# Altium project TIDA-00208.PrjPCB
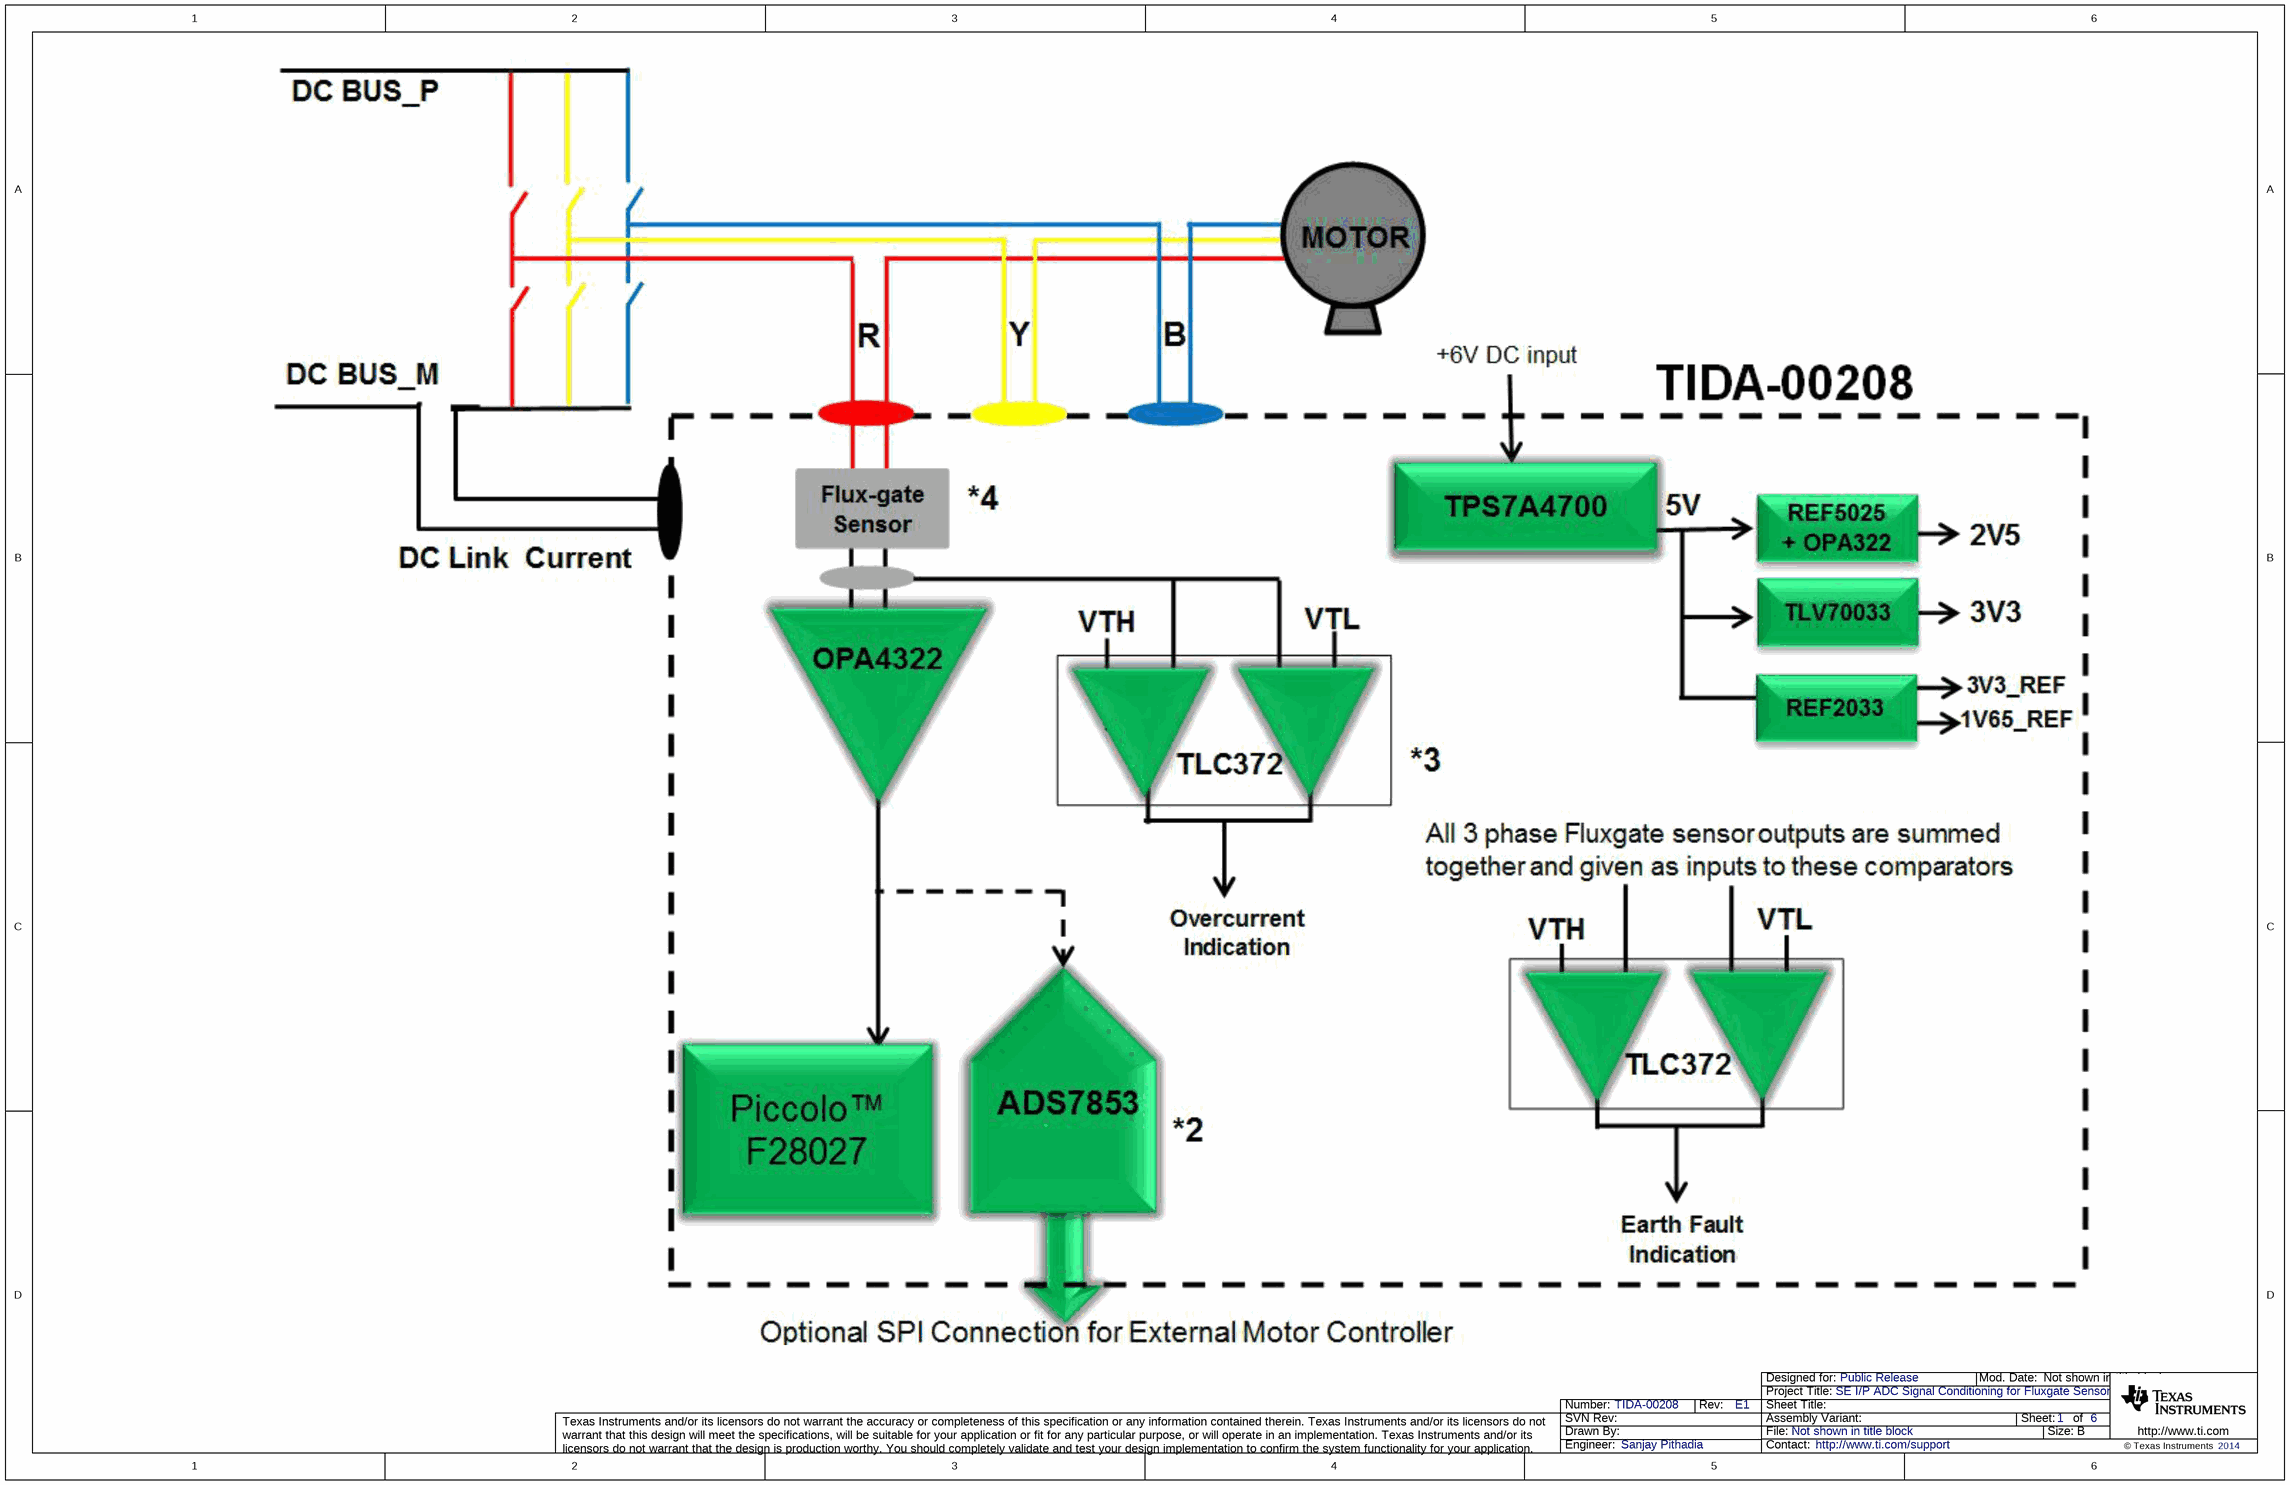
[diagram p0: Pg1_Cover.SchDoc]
TechSupport: http://www.ti.com/support; SCH_Rev: E1; PRJ_Title: SE I/P ADC Signal Conditioning for Fluxgate Sensor; PRJ_Number: TIDA-00208; PRJ_Engineer: Sanjay Pithadia; PRJ_Customer: Public Release; PCB_Rev: E2; PCB_Layout: Sharanu; CopyrightYear: 2014
6 sheets, 244 parts. Net scope: flat (ports and power ports of the same name join across sheets).
Board file: TIDA-00208.PcbDoc
Sheets:
  Pg1_Cover.SchDoc
  Pg2_Power.SchDoc
  Pg3_Channel-1_2.SchDoc
  Pg4_Channel-3_4.SchDoc
  Pg5_ADC - Connectors.SchDoc
  Pg6_Hardware_ANSI-B.SchDoc

## Sheet Pg1_Cover.SchDoc
size 431 x 279 mm; Date: Not shown in title block; ApprovedBy: Not shown in title block; CheckedBy: Not shown in title block; Author: Not shown in title block; CompanyName: Not shown in title block; Engineer: Not shown in title block; Organization: Not shown in title block; Address1: Not shown in title block; Address2: Not shown in title block; Address3: Not shown in title block; Address4: Not shown in title block; DocumentNumber: 1; Revision: Use project parameter SCH_Rev; SheetNumber: 1; SheetTotal: 6; PageSetup: Record=PageOptions|CenterHorizontal=True|CenterVertical=True|PrintScale=1.00|XCorrection=1.00|YCorrection=1.00|PrintKind=0|BorderSize=5000000|LeftOffset=0|BottomOffset=0|Orientation=2|PaperLength=1000|PaperWidth=1000|Scale=100|PaperSource=15|PrintQuality=600|MediaType=1|DitherType=10|PaperKind=Letter|PrintScaleMode=1

## Sheet Pg2_Power.SchDoc: Main
size 431 x 279 mm; Date: Not shown in title block; ApprovedBy: Not shown in title block; CheckedBy: Not shown in title block; Author: Not shown in title block; CompanyName: Not shown in title block; DrawnBy: Sanjay Pithadia; Engineer: Not shown in title block; Organization: Not shown in title block; Address1: Not shown in title block; Address2: Not shown in title block; Address3: Not shown in title block; Address4: Not shown in title block; DocumentNumber: 2; Revision: Use project parameter SCH_Rev; SheetNumber: 2; SheetTotal: 6; PageSetup: Record=PageOptions|CenterHorizontal=True|CenterVertical=True|PrintScale=1.00|XCorrection=1.00|YCorrection=1.00|PrintKind=0|BorderSize=5000000|LeftOffset=0|BottomOffset=0|Orientation=2|PaperLength=1000|PaperWidth=1000|Scale=100|PaperSource=15|PrintQuality=600|MediaType=1|DitherType=10|PaperKind=Letter|PrintScaleMode=1
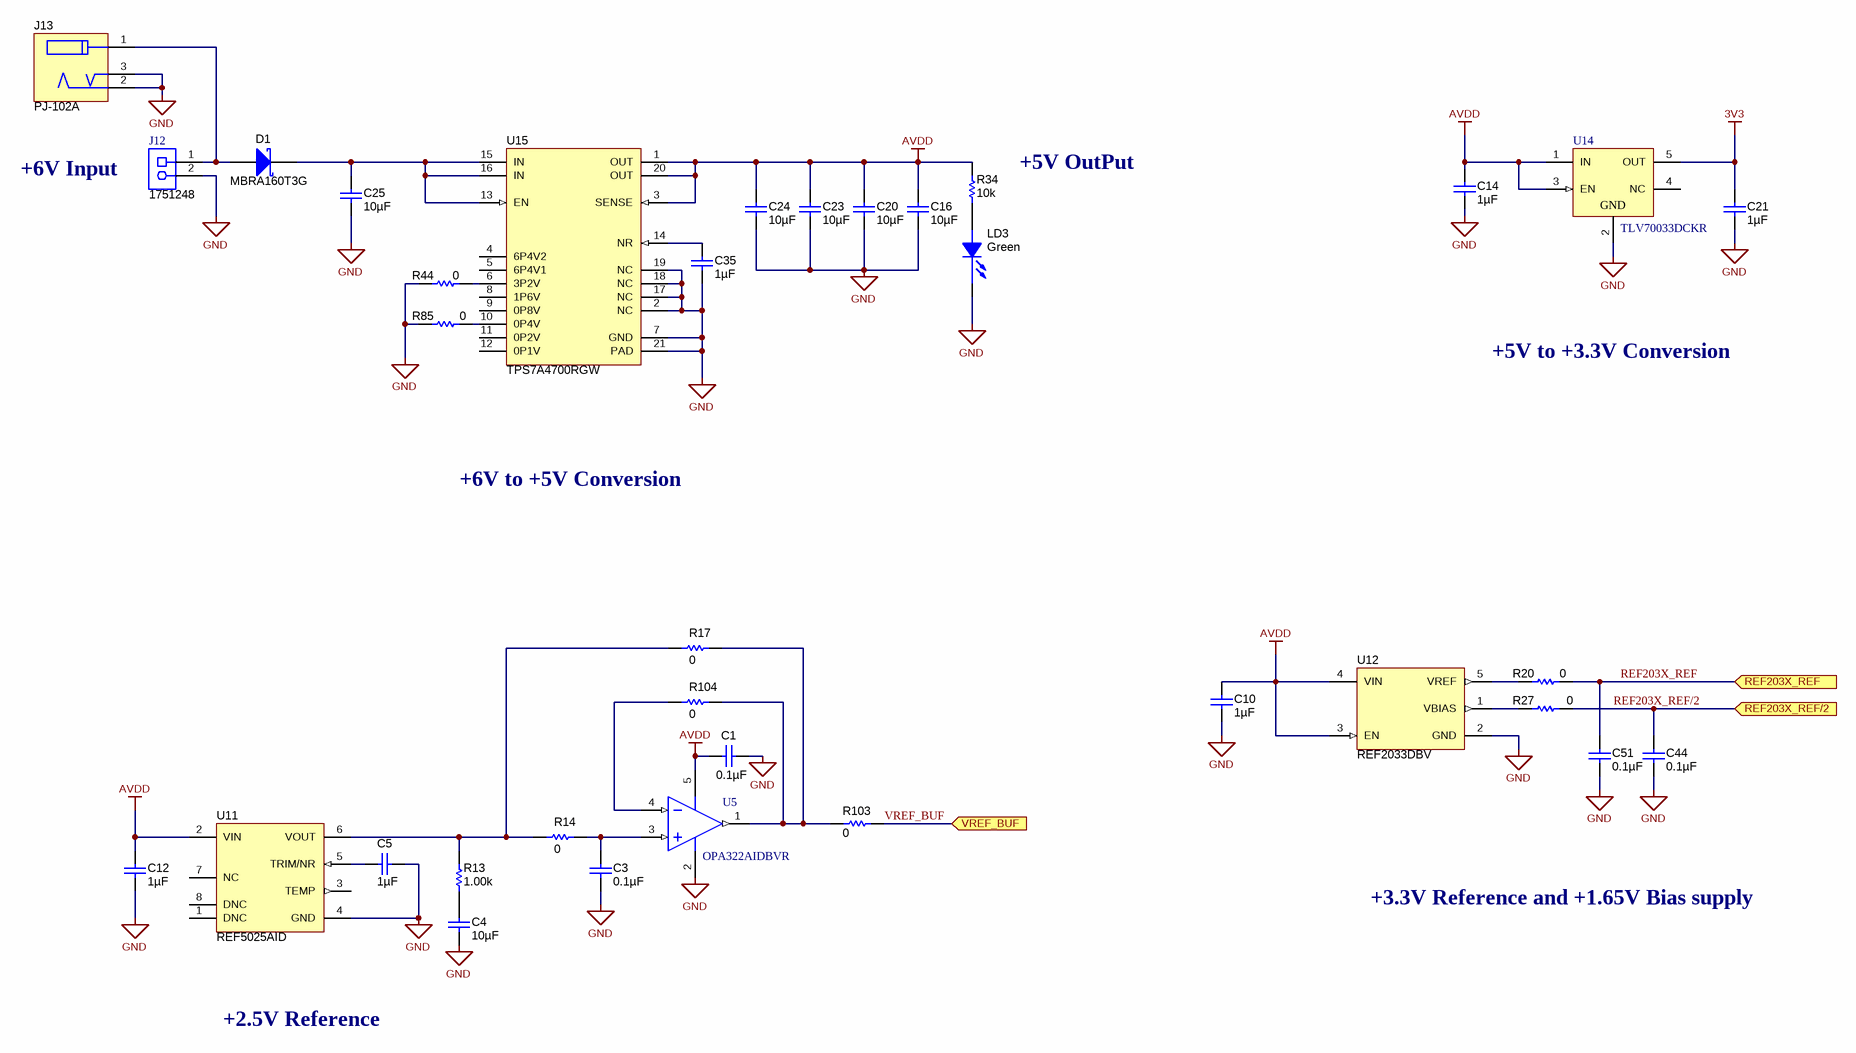
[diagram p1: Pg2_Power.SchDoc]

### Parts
C1  ValueDisplayed: 0.1µF  [0603]  (hidden comment: C0603C104J4RACTU)
C3  ValueDisplayed: 0.1µF  [0603]  (hidden comment: C0603C104K8RACTU)
C4  ValueDisplayed: 10µF  [0603]  (hidden comment: EMK107BBJ106MA-T)
C5  ValueDisplayed: 1µF  [0805_HV]  (hidden comment: C0805C105K8RACTU)
C10  ValueDisplayed: 1µF  [0805_HV]  (hidden comment: C0805C105K8RACTU)
C12  ValueDisplayed: 1µF  [0805_HV]  (hidden comment: C0805C105K8RACTU)
C14  ValueDisplayed: 1µF  [0805_HV]  (hidden comment: C0805C105K8RACTU)
C16  ValueDisplayed: 10µF  [0805_HV]  (hidden comment: GRM21BR61C106KE15L)
C20  ValueDisplayed: 10µF  [0805_HV]  (hidden comment: GRM21BR61C106KE15L)
C21  ValueDisplayed: 1µF  [0805_HV]  (hidden comment: C0805C105K8RACTU)
C23  ValueDisplayed: 10µF  [0805_HV]  (hidden comment: GRM21BR61C106KE15L)
C24  ValueDisplayed: 10µF  [0805_HV]  (hidden comment: GRM21BR61C106KE15L)
C25  ValueDisplayed: 10µF  [0805_HV]  (hidden comment: GRM21BR61C106KE15L)
C35  ValueDisplayed: 1µF  [0805_HV]  (hidden comment: C0805C105K8RACTU)
C44  ValueDisplayed: 0.1µF  [0603]  (hidden comment: C0603C104K8RACTU)
C51  ValueDisplayed: 0.1µF  [0603]  (hidden comment: C0603C104K8RACTU)
D1  MBRA160T3G  [SMA]
J12  1751248  [CONN_1751248]
J13  PJ-102A  [CONN_PJ-102A]
LD3  value Green  [LED0603AA]  (hidden comment: LED_LG L29K-G2J1-24-Z)
R13  value 1.00k  [0603]  (hidden comment: RC0603FR-071KL)
R14  value 0  [0603]  (hidden comment: CRCW06030000Z0EA)
R17  value 0  [0603]  (hidden comment: CRCW06030000Z0EA)
R20  value 0  [0603]  (hidden comment: CRCW06030000Z0EA)
R27  value 0  [0603]  (hidden comment: CRCW06030000Z0EA)
R34  value 10k  [0603]  (hidden comment: CRCW060310K0JNEA)
R44  value 0  [0603]  (hidden comment: CRCW06030000Z0EA)
R85  value 0  [0603]  (hidden comment: CRCW06030000Z0EA)
R103  value 0  [0603]  (hidden comment: CRCW06030000Z0EA)
R104  value 0  [0603]  (hidden comment: CRCW06030000Z0EA)
U5  OPA322AIDBVR  [DBV0005A_N]
U11  REF5025AID  [D0008A_N]
U12  REF2033DBV  [DBV0005A_N]
U14  TLV70033DCKR  [DCK0005A_N]
U15  TPS7A4700RGW  [RGW0020A]

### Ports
REF203X_REF (in), REF203X_REF/2 (in), VREF_BUF (in)

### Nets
3V3: C21.1 U14.5(OUT)
AVDD: C1.2 C10.1 C12.1 C14.1 C16.1 C20.1 C23.1 C24.1 R34.2 U5.5(V+) U11.2(VIN) U12.3(EN) U12.4(VIN) U14.1(IN) U14.3(EN) U15.1(OUT) U15.3(SENSE) U15.20(OUT)
GND: C1.1 C3.1 C4.2 C5.2 C10.2 C12.2 C14.2 C16.2 C20.2 C21.2 C23.2 C24.2 C25.2 C35.1 C44.1 C51.1 J12.2 J13.2 J13.3 LD3.1(C) R44.1 R85.2 U5.2(V-) U11.4(GND) U12.2(GND) U14.2(GND) U15.2(NC) U15.7(GND) U15.17(NC) U15.18(NC) U15.19(NC) U15.21(PAD)
REF203X_REF: C51.2 R20.1 ; port REF203X_REF
REF203X_REF/2: C44.2 R27.1 ; port REF203X_REF/2
VREF_BUF: R103.1 ; port VREF_BUF
NetC3_2: C3.2 R14.1 U5.3(IN+)
NetC4_1: C4.1 R13.1
NetC5_1: C5.1 U11.5(TRIM/NR)
NetC25_1: C25.1 D1.1(K) U15.13(EN) U15.15(IN) U15.16(IN)
NetC35_2: C35.2 U15.14(NR)
NetD1_2: D1.2(A) J12.1 J13.1
NetLD3_2: LD3.2(A) R34.1
NetR13_2: R13.2 R14.2 R17.2 U11.6(VOUT)
NetR17_1: R17.1 R103.2 R104.1 U5.1(OUT)
NetR20_2: R20.2 U12.5(VREF)
NetR27_2: R27.2 U12.1(VBIAS)
NetR44_2: R44.2 U15.6(3P2V)
NetR85_1: R85.1 U15.10(0P4V)
NetR104_2: R104.2 U5.4(IN-)

Not connected (* = marked no-connect by the designer): U11 1(DNC) 3(TEMP) 7(NC) 8(DNC); U14 4(NC); U15 4(6P4V2) 5(6P4V1) 8(1P6V) 9(0P8V) 11(0P2V) 12(0P1V)

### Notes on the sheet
- +6V Input
- +5V OutPut
- +5V to +3.3V Conversion
- +6V to +5V Conversion
- +3.3V Reference and +1.65V Bias supply
- +2.5V Reference

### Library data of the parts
C1 = C0603C104J4RACTU: CAP, CERM, 0.1uF, 16V, +/-5%, X7R, 0603; Manufacturer: Kemet; Polarized: N; CompType: Capacitor; U/M: EA; Cap_F: 0.0000001; Tolerance_%: 5; Value1: Unknown; VDC_V: 16; TaMin_C: -55; TaMax_C: 125
C3 C44 C51 = C0603C104K8RACTU: CAP, CERM, 0.1uF, 10V, +/-10%, X7R, 0603; Manufacturer: Kemet; Polarized: N; CompType: Capacitor; U/M: EA; Cap_F: 0.0000001; Tolerance_%: 10; Value1: Unknown; TaMin_C: -55; TaMax_C: 125
C4 = EMK107BBJ106MA-T: CAP, CERM, 10uF, 16V, +/-20%, X5R, 0603; Manufacturer: Taiyo Yuden; Polarized: N; CompType: Capacitor; U/M: EA; Cap_F: 0.00001; Tolerance_%: 20; Value1: Unknown; VDC_V: 16; TaMin_C: -55; TaMax_C: 85
C5 C10 C12 C14 C21 C35 = C0805C105K8RACTU: CAP, CERM, 1uF, 10V, +/-10%, X7R, 0805; Manufacturer: Kemet; Polarized: N; CompType: Capacitor; U/M: EA; Cap_F: 0.000001; Tolerance_%: 10; ESR_Ohm: 0.015; Value1: 0.015 ohm; IRMS_A: 8.19; TaMin_C: -55; TaMax_C: 125; Cap_Case: 0805
C16 C20 C23-C25 = GRM21BR61C106KE15L: CAP, CERM, 10uF, 16V, +/-10%, X5R, 0805; Manufacturer: MuRata; Polarized: N; CompType: Capacitor; U/M: EA; Cap_F: 0.00001; Tolerance_%: 10; ESR_Ohm: 0.008; Value1: 0.008 ohm; VDC_V: 16; TaMin_C: -55; TaMax_C: 85; Cap_Case: 0805
D1 = MBRA160T3G: Diode, Schottky, 60V, 1A, SMA; Manufacturer: ON Semiconductor; U/M: EA; Vf_V: 0.51; Value2: 0.51V; Io_A: 1; Vr_V: 60; TJmax_C: 150; RJC_CperW: 35
J12 = 1751248: Conn Term Block, 2POS, 3.5mm, TH; Manufacturer: Phoenix Contact; SymbolCreator: a0412235; Value: 2x1; CompType: Terminal Block; U/M: EA
J13 = PJ-102A: Connector, DC Jack 2.1X5.5 mm, TH; Manufacturer: CUI Inc.; SymbolCreator: a0799628; U/M: EA
LD3 = LED_LG L29K-G2J1-24-Z: LED SmartLED Green 570NM; Manufacturer: OSRAM; SymbolCreator: x0120606
R13 = RC0603FR-071KL: RES, 1.00k ohm, 1%, 0.1W, 0603; Manufacturer: Yageo America; CompType: Resistor; Res_ohm: 1000; Value_Code: 1k00; Tolerance_%: 1; Power_W: 0.1; VDC_V: 150; TempCo: 200 ppm/C; EIA_Code: E96; U/M: EA
R14 R17 R20 R27 R44 R85 R103 R104 = CRCW06030000Z0EA: RES, 0 ohm, 5%, 0.1W, 0603; Manufacturer: Vishay-Dale; CompType: Resistor; Value_Code: 0000; Tolerance_%: 5; Power_W: 0.1; VDC_V: 75; TempCo: 200 ppm/C; EIA_Code: E24; U/M: EA
R34 = CRCW060310K0JNEA: RES, 10k ohm, 5%, 0.1W, 0603; Manufacturer: Vishay-Dale; CompType: Resistor; Res_ohm: 10000; Value_Code: 10k0; Tolerance_%: 5; Power_W: 0.1; VDC_V: 75; TempCo: 200 ppm/C; EIA_Code: E24; U/M: EA
U5 = OPA322AIDBVR: 20 MHz, Low Noise, RRIO, CMOS Operational Amplifier with Shutdown, 1.8 to 5.5 V, -40 to 125 degC, 5-pin SOT23 (DBV0005A), Green (RoHS & no Sb/Br); Manufacturer: Texas Instruments; Alternate Manufacturer: None; Alternate PartNumber: Equivalent; CMRR(Min)(dB): 90; GBW(Typ)(MHz): 20; IIB(Max)(pA): 10; Iq per channel(Max)(mA): 1.9; Number of Channels: 1; Offset Drift(Typ)(uV/C): 1.8; Packing: LARGE T&R; Rating: Catalog; Sub Family: High Output Current Amplifier (>=50mA), Low Input Bias Current Amp (<=10pA), Low Noise Amp (<=10nV/rtHz), Low Supply Voltage Amplifier (<=2.7V), Precision Amplifier; Total Supply Voltage(Max)(+5V is 5, +/-5V is 10): 5.5; Vio (25C)(Max)(mV): 2
U11 = REF5025AID: Low-Noise, Very Low Drift, Precision VOLTAGE REFERENCE, 2.5V, D008A; Alternate Manufacturer: None; Manufacturer: Texas Instruments; SymbolCreator: a0411947; CompType: IC; U/M: EA
U12 = REF2033DBV: DUAL OUTPUT VOLTAGE REFERENCE 3.3V, DBV0005A; Alternate Manufacturer: None; Manufacturer: Texas Instruments; SymbolCreator: a0799628; CompType: IC; U/M: EA
U14 = TLV70033DCKR: Single Output LDO, 200 mA, Fixed 3.3 V Output, 2 to 5.5 V Input, with Low IQ, 5-pin SC70 (DCK), -40 to 125 degC, Green (RoHS & no Sb/Br); Manufacturer: Texas Instruments; Alternate Manufacturer: None; Alternate PartNumber: Equivalent; Accuracy(%): 2; Fixed Output Options(V): 3.3; Iout(Max)(A): 0.2; Iq(Typ)(mA): 0.03; SubFamily: Single Channel LDO; Vdo(Typ)(mV): 175; Vin(Max)(V): 5.5
U15 = TPS7A4700RGW: 36-V, 1-A, 4.17-µVRMS, RF LDO Voltage Regulator, RGW0020A; Alternate Manufacturer: None; Manufacturer: Texas Instruments; SymbolCreator: a0412235; CompType: IC; U/M: EA

## Sheet Pg3_Channel-1_2.SchDoc: Main
size 431 x 279 mm; Date: Not shown in title block; ApprovedBy: Not shown in title block; CheckedBy: Not shown in title block; Author: Not shown in title block; CompanyName: Not shown in title block; DrawnBy: Sanjay Pithadia; Engineer: Not shown in title block; Organization: Not shown in title block; Address1: Not shown in title block; Address2: Not shown in title block; Address3: Not shown in title block; Address4: Not shown in title block; DocumentNumber: 3; Revision: Use project parameter SCH_Rev; SheetNumber: 3; SheetTotal: 6; PageSetup: Record=PageOptions|CenterHorizontal=True|CenterVertical=True|PrintScale=1.00|XCorrection=1.00|YCorrection=1.00|PrintKind=0|BorderSize=5000000|LeftOffset=0|BottomOffset=0|Orientation=2|PaperLength=1000|PaperWidth=1000|Scale=100|PaperSource=15|PrintQuality=600|MediaType=1|DitherType=10|PaperKind=Letter|PrintScaleMode=1
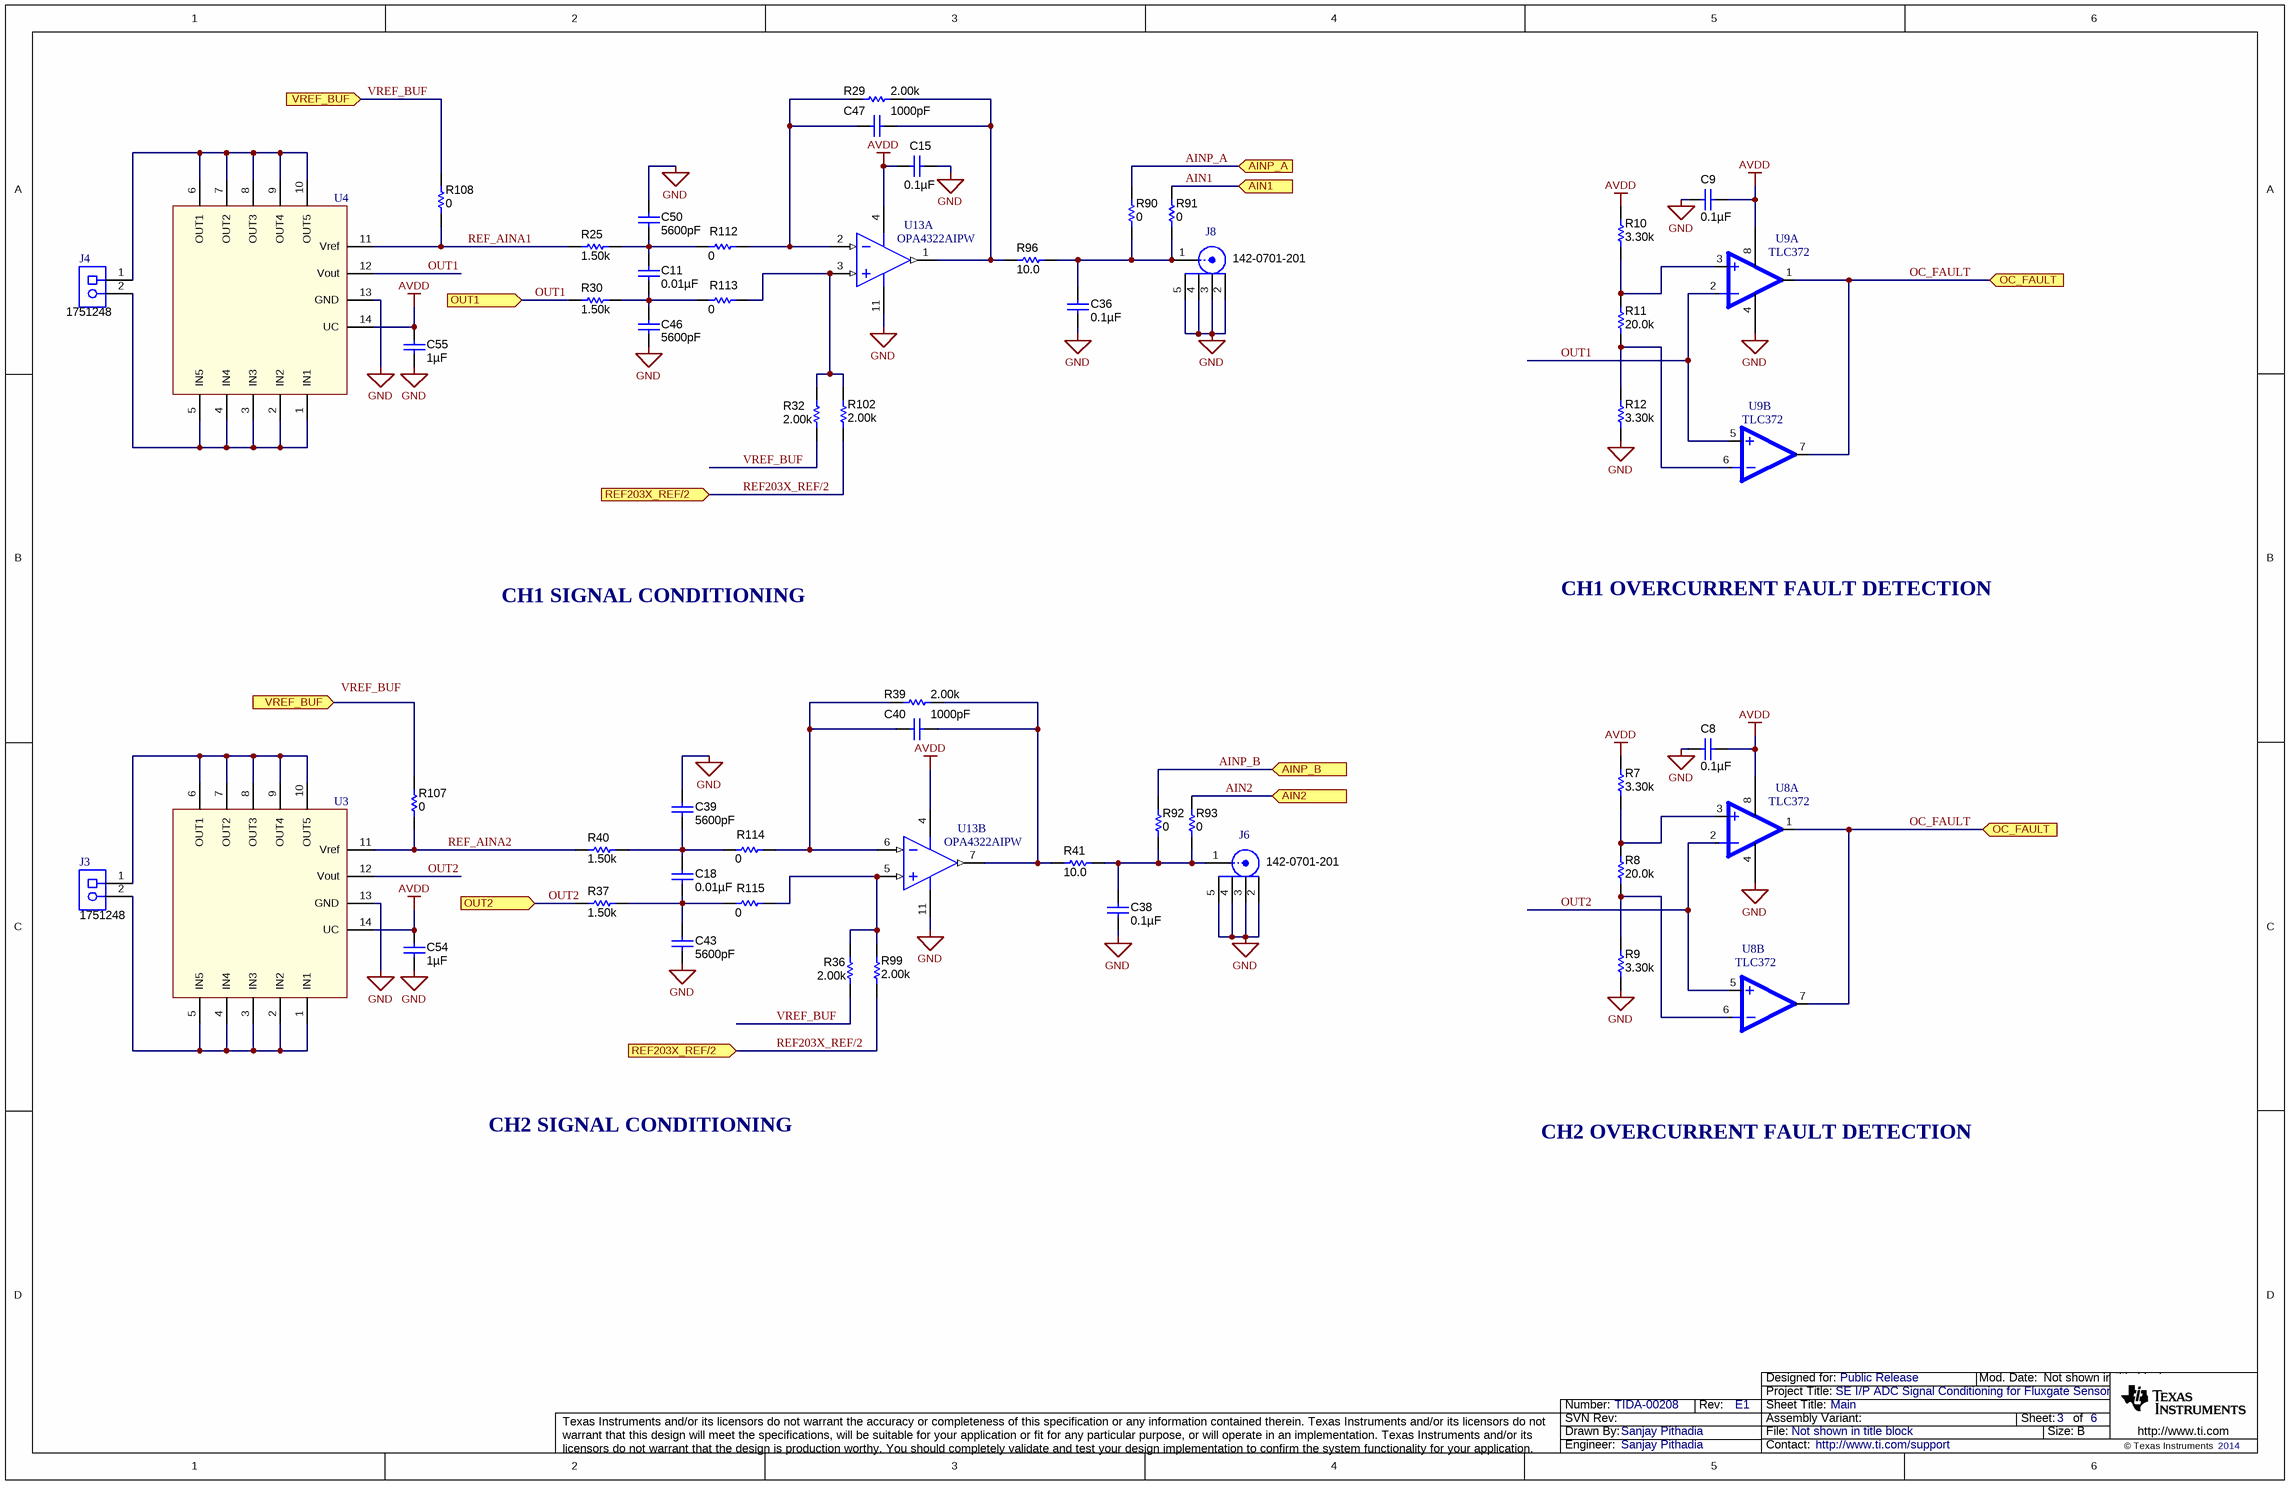
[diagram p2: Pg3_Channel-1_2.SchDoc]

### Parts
C8  ValueDisplayed: 0.1µF  [0603]  (hidden comment: C0603C104J4RACTU)
C9  ValueDisplayed: 0.1µF  [0603]  (hidden comment: C0603C104J4RACTU)
C11  ValueDisplayed: 0.01µF  [0603]  (hidden comment: C0603H103J3GACTU)
C15  ValueDisplayed: 0.1µF  [0603]  (hidden comment: C0603C104J4RACTU)
C18  ValueDisplayed: 0.01µF  [0603]  (hidden comment: C0603H103J3GACTU)
C36  ValueDisplayed: 0.1µF  [0603]  (hidden comment: C0603C104J4RACTU)
C38  ValueDisplayed: 0.1µF  [0603]  (hidden comment: C0603C104J4RACTU)
C39  ValueDisplayed: 5600pF  [0603]  (hidden comment: C1608C0G1E562J)
C40  ValueDisplayed: 1000pF  [0603]  (hidden comment: GRM1885C1E102JA01D)
C43  ValueDisplayed: 5600pF  [0603]  (hidden comment: C1608C0G1E562J)
C46  ValueDisplayed: 5600pF  [0603]  (hidden comment: C1608C0G1E562J)
C47  ValueDisplayed: 1000pF  [0603]  (hidden comment: GRM1885C1E102JA01D)
C50  ValueDisplayed: 5600pF  [0603]  (hidden comment: C1608C0G1E562J)
C54  ValueDisplayed: 1µF  [0603]  (hidden comment: GRM188R71E105KA12D)
C55  ValueDisplayed: 1µF  [0603]  (hidden comment: GRM188R71E105KA12D)
J3  1751248  [CONN_1751248]
J4  1751248  [CONN_1751248]
J6  142-0701-201  [Johnson_142-0701-20x]
J8  142-0701-201  [Johnson_142-0701-20x]
R7  value 3.30k  [0603]  (hidden comment: RC0603FR-073K3L)
R8  value 20.0k  [0603]  (hidden comment: CRCW060320K0FKEA)
R9  value 3.30k  [0603]  (hidden comment: RC0603FR-073K3L)
R10  value 3.30k  [0603]  (hidden comment: RC0603FR-073K3L)
R11  value 20.0k  [0603]  (hidden comment: CRCW060320K0FKEA)
R12  value 3.30k  [0603]  (hidden comment: RC0603FR-073K3L)
R25  ValueDisplayed: 1.50k  [0603]  (hidden comment: CRCW06031K50FKEA)
R29  ValueDisplayed: 2.00k  [0603]  (hidden comment: CRCW06032K00FKEA)
R30  ValueDisplayed: 1.50k  [0603]  (hidden comment: CRCW06031K50FKEA)
R32  ValueDisplayed: 2.00k  [0603]  (hidden comment: CRCW06032K00FKEA)
R36  ValueDisplayed: 2.00k  [0603]  (hidden comment: CRCW06032K00FKEA)
R37  ValueDisplayed: 1.50k  [0603]  (hidden comment: CRCW06031K50FKEA)
R39  ValueDisplayed: 2.00k  [0603]  (hidden comment: CRCW06032K00FKEA)
R40  ValueDisplayed: 1.50k  [0603]  (hidden comment: CRCW06031K50FKEA)
R41  value 10.0  [0603]  (hidden comment: RT0603BRD0710RL)
R90  value 0  [0603]  (hidden comment: CRCW06030000Z0EA)
R91  value 0  [0603]  (hidden comment: CRCW06030000Z0EA)
R92  value 0  [0603]  (hidden comment: CRCW06030000Z0EA)
R93  value 0  [0603]  (hidden comment: CRCW06030000Z0EA)
R96  value 10.0  [0603]  (hidden comment: RT0603BRD0710RL)
R99  ValueDisplayed: 2.00k  [0603]  (hidden comment: CRCW06032K00FKEA)
R102  ValueDisplayed: 2.00k  [0603]  (hidden comment: CRCW06032K00FKEA)
R107  value 0  [0603]  (hidden comment: CRCW06030000Z0EA)
R108  value 0  [0603]  (hidden comment: CRCW06030000Z0EA)
R112  value 0  [0603]  (hidden comment: CRCW06030000Z0EA)
R113  value 0  [0603]  (hidden comment: CRCW06030000Z0EA)
R114  value 0  [0603]  (hidden comment: CRCW06030000Z0EA)
R115  value 0  [0603]  (hidden comment: CRCW06030000Z0EA)
U3  SENSOR_CKSR X-NP  [CKSR X-NP]  (value not drawn)
U4  SENSOR_CKSR X-NP  [CKSR X-NP]  (value not drawn)
U8  TLC372  [SO8]  (parts A,B of 2)
U9  TLC372  [SO8]  (parts A,B of 2)
U13  OPA4322AIPW  [PW0014A_N]  (parts A,B of 4)

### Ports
AIN1 (in), AIN2 (in), AINP_A (in), AINP_B (in), OC_FAULT (in), OUT1 (in), OUT2 (in), REF203X_REF/2 (in), VREF_BUF (in)

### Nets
AVDD: C8.1 C9.1 C15.2 C54.2 C55.2 R7.2 R10.2 U3.14(UC) U4.14(UC) U8.8(VCC) U9.8(VCC) U13.4(V+)
GND: C8.2 C9.2 C15.1 C36.2 C38.2 C39.2 C43.2 C46.2 C50.2 C54.1 C55.1 J6.2 J6.3 J6.4 J6.5 J8.2 J8.3 J8.4 J8.5 R9.1 R12.1 U3.13(GND) U4.13(GND) U8.4(GND) U9.4(GND) U13.11(V-)
AIN1: R91.2 ; port AIN1
AIN2: R93.2 ; port AIN2
AINP_A: R90.2 ; port AINP_A
AINP_B: R92.2 ; port AINP_B
OC_FAULT: U8.1(OUT) U8.7(OUT) U9.1(OUT) U9.7(OUT) ; port OC_FAULT
OUT1: R30.1 U4.12(Vout) U9.2(IN-) U9.5(IN+) ; port OUT1
OUT2: R37.1 U3.12(Vout) U8.2(IN-) U8.5(IN+) ; port OUT2
REF203X_REF/2: R99.1 R102.1 ; port REF203X_REF/2
REF_AINA1: R25.1 R108.1 U4.11(Vref)
REF_AINA2: R40.1 R107.1 U3.11(Vref)
VREF_BUF: R32.1 R36.1 R107.2 R108.2 ; port VREF_BUF
NetC11_1: C11.1 C46.1 R30.2 R113.2
NetC11_2: C11.2 C50.1 R25.2 R112.2
NetC18_1: C18.1 C39.1 R40.2 R114.2
NetC18_2: C18.2 C43.1 R37.2 R115.2
NetC36_1: C36.1 J8.1 R90.1 R91.1 R96.2
NetC38_1: C38.1 J6.1 R41.2 R92.1 R93.1
NetC40_1: C40.1 R39.2 R41.1 U13.7(OUT_B)
NetC40_2: C40.2 R39.1 R114.1 U13.6(IN_B-)
NetC47_1: C47.1 R29.2 R96.1 U13.1(OUT_A)
NetC47_2: C47.2 R29.1 R112.1 U13.2(IN_A-)
NetJ3_1: J3.1 U3.6(OUT1) U3.7(OUT2) U3.8(OUT3) U3.9(OUT4) U3.10(OUT5)
NetJ3_2: J3.2 U3.1(IN1) U3.2(IN2) U3.3(IN3) U3.4(IN4) U3.5(IN5)
NetJ4_1: J4.1 U4.6(OUT1) U4.7(OUT2) U4.8(OUT3) U4.9(OUT4) U4.10(OUT5)
NetJ4_2: J4.2 U4.1(IN1) U4.2(IN2) U4.3(IN3) U4.4(IN4) U4.5(IN5)
NetR7_1: R7.1 R8.2 U8.3(IN+)
NetR8_1: R8.1 R9.2 U8.6(IN-)
NetR10_1: R10.1 R11.2 U9.3(IN+)
NetR11_1: R11.1 R12.2 U9.6(IN-)
NetR32_2: R32.2 R102.2 R113.1 U13.3(IN_A+)
NetR36_2: R36.2 R99.2 R115.1 U13.5(IN_B+)

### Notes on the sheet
- CH1 SIGNAL CONDITIONING
- CH1 OVERCURRENT FAULT DETECTION
- CH2 SIGNAL CONDITIONING
- CH2 OVERCURRENT FAULT DETECTION
- Labels drawn without touching a wire or pin: VREF_BUF

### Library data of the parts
C8 C9 C15 C36 C38 = C0603C104J4RACTU: as C1 on sheet Pg2_Power
C11 C18 = C0603H103J3GACTU: CAP, CERM, 0.01uF, 25V, +/-5%, C0G/NP0, 0603; Manufacturer: Kemet; Polarized: N; CompType: Capacitor; U/M: EA; Cap_F: 0.00000001; Tolerance_%: 5; Value1: Unknown; VDC_V: 25; TaMin_C: -55; TaMax_C: 200
C39 C43 C46 C50 = C1608C0G1E562J: CAP, CERM, 5600pF, 25V, +/-5%, C0G/NP0, 0603; Manufacturer: TDK; Polarized: N; CompType: Capacitor; U/M: EA; Cap_F: 0.0000000056; Tolerance_%: 5; Value1: Unknown; VDC_V: 25; TaMin_C: -55; TaMax_C: 125
C40 C47 = GRM1885C1E102JA01D: CAP, CERM, 1000pF, 25V, +/-5%, C0G/NP0, 0603; Manufacturer: MuRata; Polarized: N; CompType: Capacitor; U/M: EA; Cap_F: 0.000000001; Tolerance_%: 5; Value1: Unknown; VDC_V: 25; TaMin_C: -55; TaMax_C: 125
C54 C55 = GRM188R71E105KA12D: CAP, CERM, 1uF, 25V, +/-10%, X7R, 0603; Manufacturer: MuRata; Polarized: N; CompType: Capacitor; U/M: EA; Cap_F: 0.000001; Tolerance_%: 10; Value1: Unknown; VDC_V: 25; TaMin_C: -55; TaMax_C: 125
J3 J4 = 1751248: as J12 on sheet Pg2_Power
J6 J8 = 142-0701-201: Connector, TH, SMA; Manufacturer: Emerson Network Power; SymbolCreator: X0208326; U/M: EA
R7 R9 R10 R12 = RC0603FR-073K3L: RES, 3.30k ohm, 1%, 0.1W, 0603; Manufacturer: Yageo America; CompType: Resistor; Res_ohm: 3300; Value_Code: 3k30; Tolerance_%: 1; Power_W: 0.1; VDC_V: 150; TempCo: 200 ppm/C; U/M: EA
R8 R11 = CRCW060320K0FKEA: RES, 20.0k ohm, 1%, 0.1W, 0603; Manufacturer: Vishay-Dale; CompType: Resistor; Res_ohm: 20000; Value_Code: 20k0; Tolerance_%: 1; Power_W: 0.1; VDC_V: 75; TempCo: 100 ppm/C; EIA_Code: E96; U/M: EA
R25 R30 R37 R40 = CRCW06031K50FKEA: RES, 1.50 k, 1%, 0.1 W, 0603; Manufacturer: Vishay-Dale; CompType: Resistor; Value: 1.50k; Res_ohm: 1500; Value_Code: 1k50; Tolerance_%: 1; Power_W: 0.1; Value2: 0.1W; VDC_V: 75; TempCo: 100 ppm/C; EIA_Code: E96; U/M: EA
R29 R32 R36 R39 R99 R102 = CRCW06032K00FKEA: RES, 2.00 k, 1%, 0.1 W, 0603; Manufacturer: Vishay-Dale; CompType: Resistor; Value: 2.00k; Res_ohm: 2000; Value_Code: 2k00; Tolerance_%: 1; Power_W: 0.1; Value2: 0.1W; VDC_V: 75; TempCo: 100 ppm/C; EIA_Code: E96; U/M: EA
R41 R96 = RT0603BRD0710RL: RES, 10.0 ohm, 0.1%, 0.1W, 0603; Manufacturer: Yageo America; CompType: Resistor; Res_ohm: 10; Value_Code: 10R0; Tolerance_%: 0.1; VDC_V: 75; TempCo: 25 ppm/C; EIA_Code: E192; U/M: EA
R90-R93 R107 R108 R112-R115 = CRCW06030000Z0EA: as R14 on sheet Pg2_Power
U3 U4 = SENSOR_CKSR X-NP: SENSOR CURRENT 50A 5V MOD; Manufacturer: LEM USA Inc; CompType: Current Transducers
U8 U9 = LM393D: IC, Dual Differential Comparators, 2-36 Vin; Manufacturer: TI; Alternate Manufacturer: None; Area: 75900
U13 = OPA4322AIPW: 20 MHz, Low Noise, RRIO, CMOS Operational Amplifier, 1.8 to 5.5 V, -40 to 125 degC, 14-pin SOP (PW0014A), Green (RoHS & no Sb/Br); Manufacturer: Texas Instruments; Alternate Manufacturer: None; Alternate PartNumber: Equivalent; CMRR(Min)(dB): 90; GBW(Typ)(MHz): 20; IIB(Max)(pA): 10; Iq per channel(Max)(mA): 1.65; Number of Channels: 4; Offset Drift(Typ)(uV/C): 1.8; Packing: TUBE; Rating: Catalog; Sub Family: High Output Current Amplifier (>=50mA), Low Input Bias Current Amp (<=10pA), Low Noise Amp (<=10nV/rtHz), Low Supply Voltage Amplifier (<=2.7V), Precision Amplifier; Total Supply Voltage(Max)(+5V is 5, +/-5V is 10): 5.5; Vio (25C)(Max)(mV): 2

## Sheet Pg4_Channel-3_4.SchDoc: Main
size 431 x 279 mm; Date: Not shown in title block; ApprovedBy: Not shown in title block; CheckedBy: Not shown in title block; Author: Not shown in title block; CompanyName: Not shown in title block; DrawnBy: Sanjay Pithadia; Engineer: Not shown in title block; Organization: Not shown in title block; Address1: Not shown in title block; Address2: Not shown in title block; Address3: Not shown in title block; Address4: Not shown in title block; DocumentNumber: 4; Revision: Use project parameter SCH_Rev; SheetNumber: 4; SheetTotal: 6; PageSetup: Record=PageOptions|CenterHorizontal=True|CenterVertical=True|PrintScale=1.00|XCorrection=1.00|YCorrection=1.00|PrintKind=0|BorderSize=5000000|LeftOffset=0|BottomOffset=0|Orientation=2|PaperLength=1000|PaperWidth=1000|Scale=100|PaperSource=15|PrintQuality=600|MediaType=1|DitherType=10|PaperKind=Letter|PrintScaleMode=1
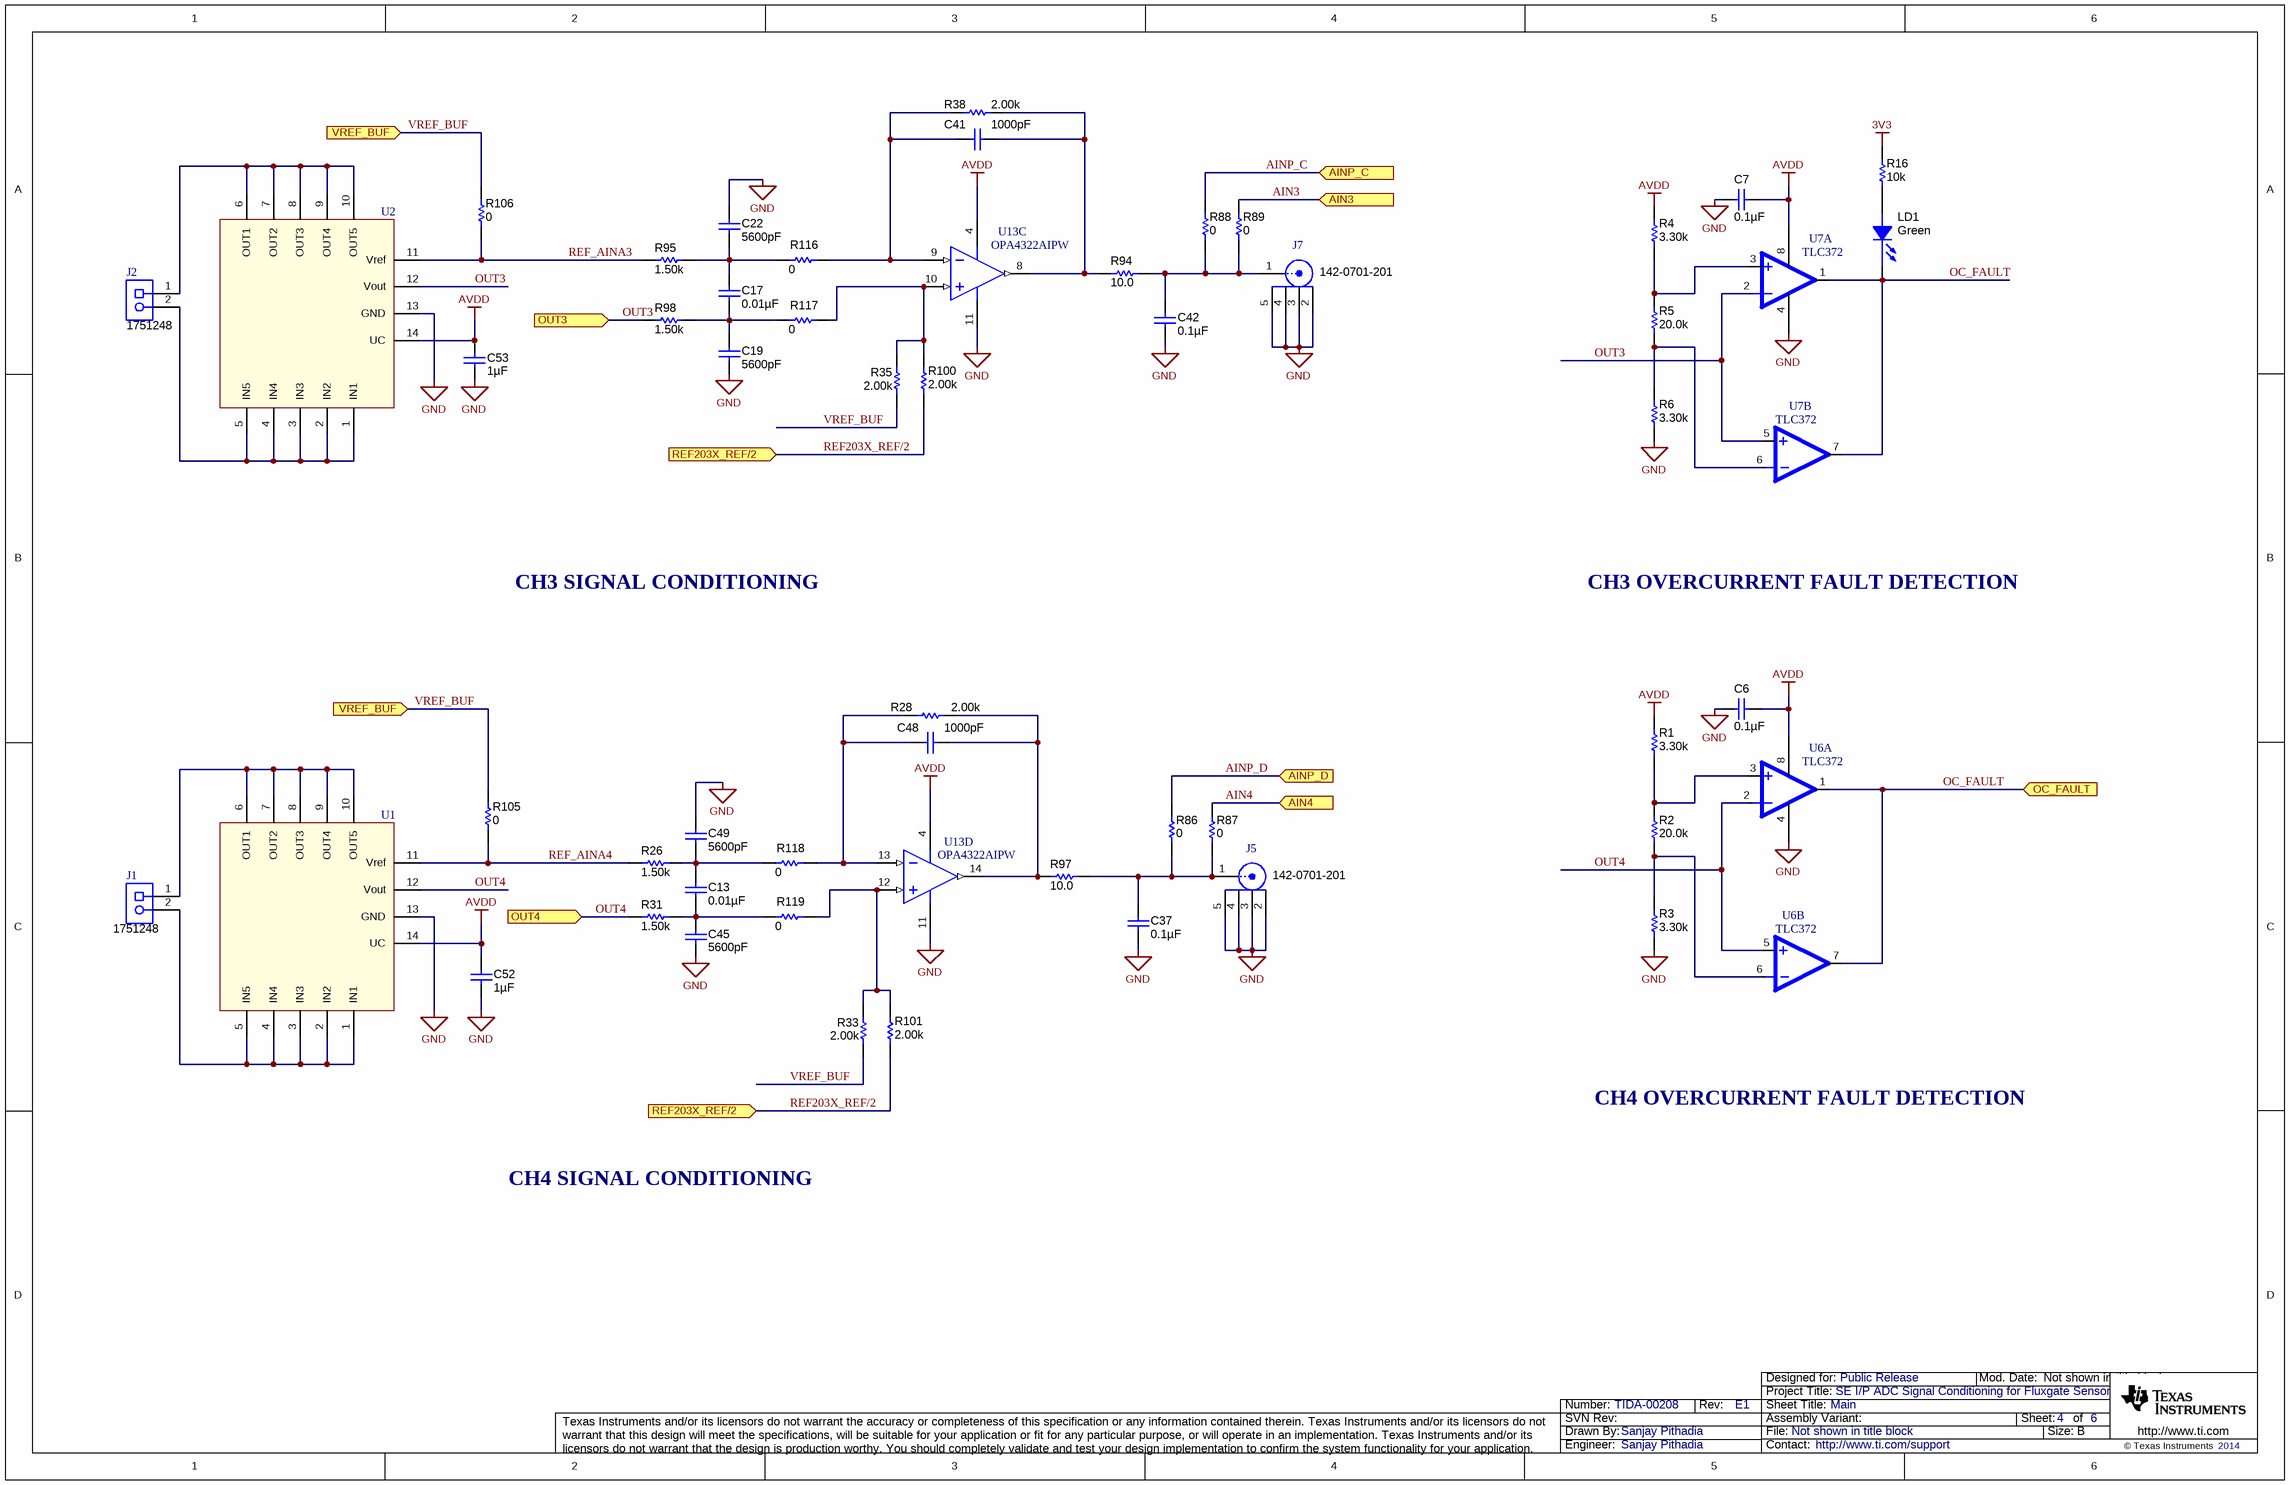
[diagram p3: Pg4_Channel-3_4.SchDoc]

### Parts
C6  ValueDisplayed: 0.1µF  [0603]  (hidden comment: C0603C104J4RACTU)
C7  ValueDisplayed: 0.1µF  [0603]  (hidden comment: C0603C104J4RACTU)
C13  ValueDisplayed: 0.01µF  [0603]  (hidden comment: C0603H103J3GACTU)
C17  ValueDisplayed: 0.01µF  [0603]  (hidden comment: C0603H103J3GACTU)
C19  ValueDisplayed: 5600pF  [0603]  (hidden comment: C1608C0G1E562J)
C22  ValueDisplayed: 5600pF  [0603]  (hidden comment: C1608C0G1E562J)
C37  ValueDisplayed: 0.1µF  [0603]  (hidden comment: C0603C104J4RACTU)
C41  ValueDisplayed: 1000pF  [0603]  (hidden comment: GRM1885C1E102JA01D)
C42  ValueDisplayed: 0.1µF  [0603]  (hidden comment: C0603C104J4RACTU)
C45  ValueDisplayed: 5600pF  [0603]  (hidden comment: C1608C0G1E562J)
C48  ValueDisplayed: 1000pF  [0603]  (hidden comment: GRM1885C1E102JA01D)
C49  ValueDisplayed: 5600pF  [0603]  (hidden comment: C1608C0G1E562J)
C52  ValueDisplayed: 1µF  [0603]  (hidden comment: GRM188R71E105KA12D)
C53  ValueDisplayed: 1µF  [0603]  (hidden comment: GRM188R71E105KA12D)
J1  1751248  [CONN_1751248]
J2  1751248  [CONN_1751248]
J5  142-0701-201  [Johnson_142-0701-20x]
J7  142-0701-201  [Johnson_142-0701-20x]
LD1  value Green  [LED0603AA]  (hidden comment: LED_LG L29K-G2J1-24-Z)
R1  value 3.30k  [0603]  (hidden comment: RC0603FR-073K3L)
R2  value 20.0k  [0603]  (hidden comment: CRCW060320K0FKEA)
R3  value 3.30k  [0603]  (hidden comment: RC0603FR-073K3L)
R4  value 3.30k  [0603]  (hidden comment: RC0603FR-073K3L)
R5  value 20.0k  [0603]  (hidden comment: CRCW060320K0FKEA)
R6  value 3.30k  [0603]  (hidden comment: RC0603FR-073K3L)
R16  value 10k  [0603]  (hidden comment: CRCW060310K0JNEA)
R26  ValueDisplayed: 1.50k  [0603]  (hidden comment: CRCW06031K50FKEA)
R28  ValueDisplayed: 2.00k  [0603]  (hidden comment: CRCW06032K00FKEA)
R31  ValueDisplayed: 1.50k  [0603]  (hidden comment: CRCW06031K50FKEA)
R33  ValueDisplayed: 2.00k  [0603]  (hidden comment: CRCW06032K00FKEA)
R35  ValueDisplayed: 2.00k  [0603]  (hidden comment: CRCW06032K00FKEA)
R38  ValueDisplayed: 2.00k  [0603]  (hidden comment: CRCW06032K00FKEA)
R86  value 0  [0603]  (hidden comment: CRCW06030000Z0EA)
R87  value 0  [0603]  (hidden comment: CRCW06030000Z0EA)
R88  value 0  [0603]  (hidden comment: CRCW06030000Z0EA)
R89  value 0  [0603]  (hidden comment: CRCW06030000Z0EA)
R94  value 10.0  [0603]  (hidden comment: RT0603BRD0710RL)
R95  ValueDisplayed: 1.50k  [0603]  (hidden comment: CRCW06031K50FKEA)
R97  value 10.0  [0603]  (hidden comment: RT0603BRD0710RL)
R98  ValueDisplayed: 1.50k  [0603]  (hidden comment: CRCW06031K50FKEA)
R100  ValueDisplayed: 2.00k  [0603]  (hidden comment: CRCW06032K00FKEA)
R101  ValueDisplayed: 2.00k  [0603]  (hidden comment: CRCW06032K00FKEA)
R105  value 0  [0603]  (hidden comment: CRCW06030000Z0EA)
R106  value 0  [0603]  (hidden comment: CRCW06030000Z0EA)
R116  value 0  [0603]  (hidden comment: CRCW06030000Z0EA)
R117  value 0  [0603]  (hidden comment: CRCW06030000Z0EA)
R118  value 0  [0603]  (hidden comment: CRCW06030000Z0EA)
R119  value 0  [0603]  (hidden comment: CRCW06030000Z0EA)
U1  SENSOR_CKSR X-NP  [CKSR X-NP]  (value not drawn)
U2  SENSOR_CKSR X-NP  [CKSR X-NP]  (value not drawn)
U6  TLC372  [SO8]  (parts A,B of 2)
U7  TLC372  [SO8]  (parts A,B of 2)
U13  OPA4322AIPW  [PW0014A_N]  (parts C,D of 4)

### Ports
AIN3 (in), AIN4 (in), AINP_C (in), AINP_D (in), OC_FAULT (in), OUT3 (in), OUT4 (in), REF203X_REF/2 (in), VREF_BUF (in)

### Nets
3V3: R16.2
AVDD: C6.1 C7.1 C52.2 C53.2 R1.2 R4.2 U1.14(UC) U2.14(UC) U6.8(VCC) U7.8(VCC) U13.4(V+)
GND: C6.2 C7.2 C19.2 C22.2 C37.2 C42.2 C45.2 C49.2 C52.1 C53.1 J5.2 J5.3 J5.4 J5.5 J7.2 J7.3 J7.4 J7.5 R3.1 R6.1 U1.13(GND) U2.13(GND) U6.4(GND) U7.4(GND) U13.11(V-)
AIN3: R89.2 ; port AIN3
AIN4: R87.2 ; port AIN4
AINP_C: R88.2 ; port AINP_C
AINP_D: R86.2 ; port AINP_D
OC_FAULT: LD1.1(C) U6.1(OUT) U6.7(OUT) U7.1(OUT) U7.7(OUT) ; port OC_FAULT
OUT3: R98.1 U2.12(Vout) U7.2(IN-) U7.5(IN+) ; port OUT3
OUT4: R31.1 U1.12(Vout) U6.2(IN-) U6.5(IN+) ; port OUT4
REF203X_REF/2: R100.1 R101.1 ; port REF203X_REF/2
REF_AINA3: R95.1 R106.1 U2.11(Vref)
REF_AINA4: R26.1 R105.1 U1.11(Vref)
VREF_BUF: R33.1 R35.1 R105.2 R106.2 ; port VREF_BUF
NetC13_1: C13.1 C45.1 R31.2 R119.2
NetC13_2: C13.2 C49.1 R26.2 R118.2
NetC17_1: C17.1 C19.1 R98.2 R117.2
NetC17_2: C17.2 C22.1 R95.2 R116.2
NetC37_1: C37.1 J5.1 R86.1 R87.1 R97.2
NetC41_1: C41.1 R38.2 R94.1 U13.8(OUT_C)
NetC41_2: C41.2 R38.1 R116.1 U13.9(IN_C-)
NetC42_1: C42.1 J7.1 R88.1 R89.1 R94.2
NetC48_1: C48.1 R28.2 R97.1 U13.14(OUT_D)
NetC48_2: C48.2 R28.1 R118.1 U13.13(IN_D-)
NetJ1_1: J1.1 U1.6(OUT1) U1.7(OUT2) U1.8(OUT3) U1.9(OUT4) U1.10(OUT5)
NetJ1_2: J1.2 U1.1(IN1) U1.2(IN2) U1.3(IN3) U1.4(IN4) U1.5(IN5)
NetJ2_1: J2.1 U2.6(OUT1) U2.7(OUT2) U2.8(OUT3) U2.9(OUT4) U2.10(OUT5)
NetJ2_2: J2.2 U2.1(IN1) U2.2(IN2) U2.3(IN3) U2.4(IN4) U2.5(IN5)
NetLD1_2: LD1.2(A) R16.1
NetR1_1: R1.1 R2.2 U6.3(IN+)
NetR2_1: R2.1 R3.2 U6.6(IN-)
NetR4_1: R4.1 R5.2 U7.3(IN+)
NetR5_1: R5.1 R6.2 U7.6(IN-)
NetR33_2: R33.2 R101.2 R119.1 U13.12(IN_D+)
NetR35_2: R35.2 R100.2 R117.1 U13.10(IN_C+)

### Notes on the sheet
- CH3 SIGNAL CONDITIONING
- CH3 OVERCURRENT FAULT DETECTION
- CH4 OVERCURRENT FAULT DETECTION
- CH4 SIGNAL CONDITIONING

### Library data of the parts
C6 C7 C37 C42 = C0603C104J4RACTU: as C1 on sheet Pg2_Power
C13 C17 = C0603H103J3GACTU: as C11 on sheet Pg3_Channel-1_2
C19 C22 C45 C49 = C1608C0G1E562J: as C39 on sheet Pg3_Channel-1_2
C41 C48 = GRM1885C1E102JA01D: as C40 on sheet Pg3_Channel-1_2
C52 C53 = GRM188R71E105KA12D: as C54 on sheet Pg3_Channel-1_2
J1 J2 = 1751248: as J12 on sheet Pg2_Power
J5 J7 = 142-0701-201: as J6 on sheet Pg3_Channel-1_2
LD1 = LED_LG L29K-G2J1-24-Z: as LD3 on sheet Pg2_Power
R1 R3 R4 R6 = RC0603FR-073K3L: as R7 on sheet Pg3_Channel-1_2
R2 R5 = CRCW060320K0FKEA: as R8 on sheet Pg3_Channel-1_2
R16 = CRCW060310K0JNEA: as R34 on sheet Pg2_Power
R26 R31 R95 R98 = CRCW06031K50FKEA: as R25 on sheet Pg3_Channel-1_2
R28 R33 R35 R38 R100 R101 = CRCW06032K00FKEA: as R29 on sheet Pg3_Channel-1_2
R86-R89 R105 R106 R116-R119 = CRCW06030000Z0EA: as R14 on sheet Pg2_Power
R94 R97 = RT0603BRD0710RL: as R41 on sheet Pg3_Channel-1_2
U1 U2 = SENSOR_CKSR X-NP: as U3 on sheet Pg3_Channel-1_2
U6 U7 = LM393D: as U8 on sheet Pg3_Channel-1_2
U13 = OPA4322AIPW: as U13 on sheet Pg3_Channel-1_2

## Sheet Pg5_ADC - Connectors.SchDoc: Main
size 431 x 279 mm; Date: Not shown in title block; ApprovedBy: Not shown in title block; CheckedBy: Not shown in title block; Author: Not shown in title block; CompanyName: Not shown in title block; DrawnBy: Sanjay Pithadia; Engineer: Not shown in title block; Organization: Not shown in title block; Address1: Not shown in title block; Address2: Not shown in title block; Address3: Not shown in title block; Address4: Not shown in title block; DocumentNumber: 5; Revision: Use project parameter SCH_Rev; SheetNumber: 5; SheetTotal: 6; PageSetup: Record=PageOptions|CenterHorizontal=True|CenterVertical=True|PrintScale=1.00|XCorrection=1.00|YCorrection=1.00|PrintKind=0|BorderSize=5000000|LeftOffset=0|BottomOffset=0|Orientation=2|PaperLength=1000|PaperWidth=1000|Scale=100|PaperSource=15|PrintQuality=600|MediaType=1|DitherType=10|PaperKind=Letter|PrintScaleMode=1
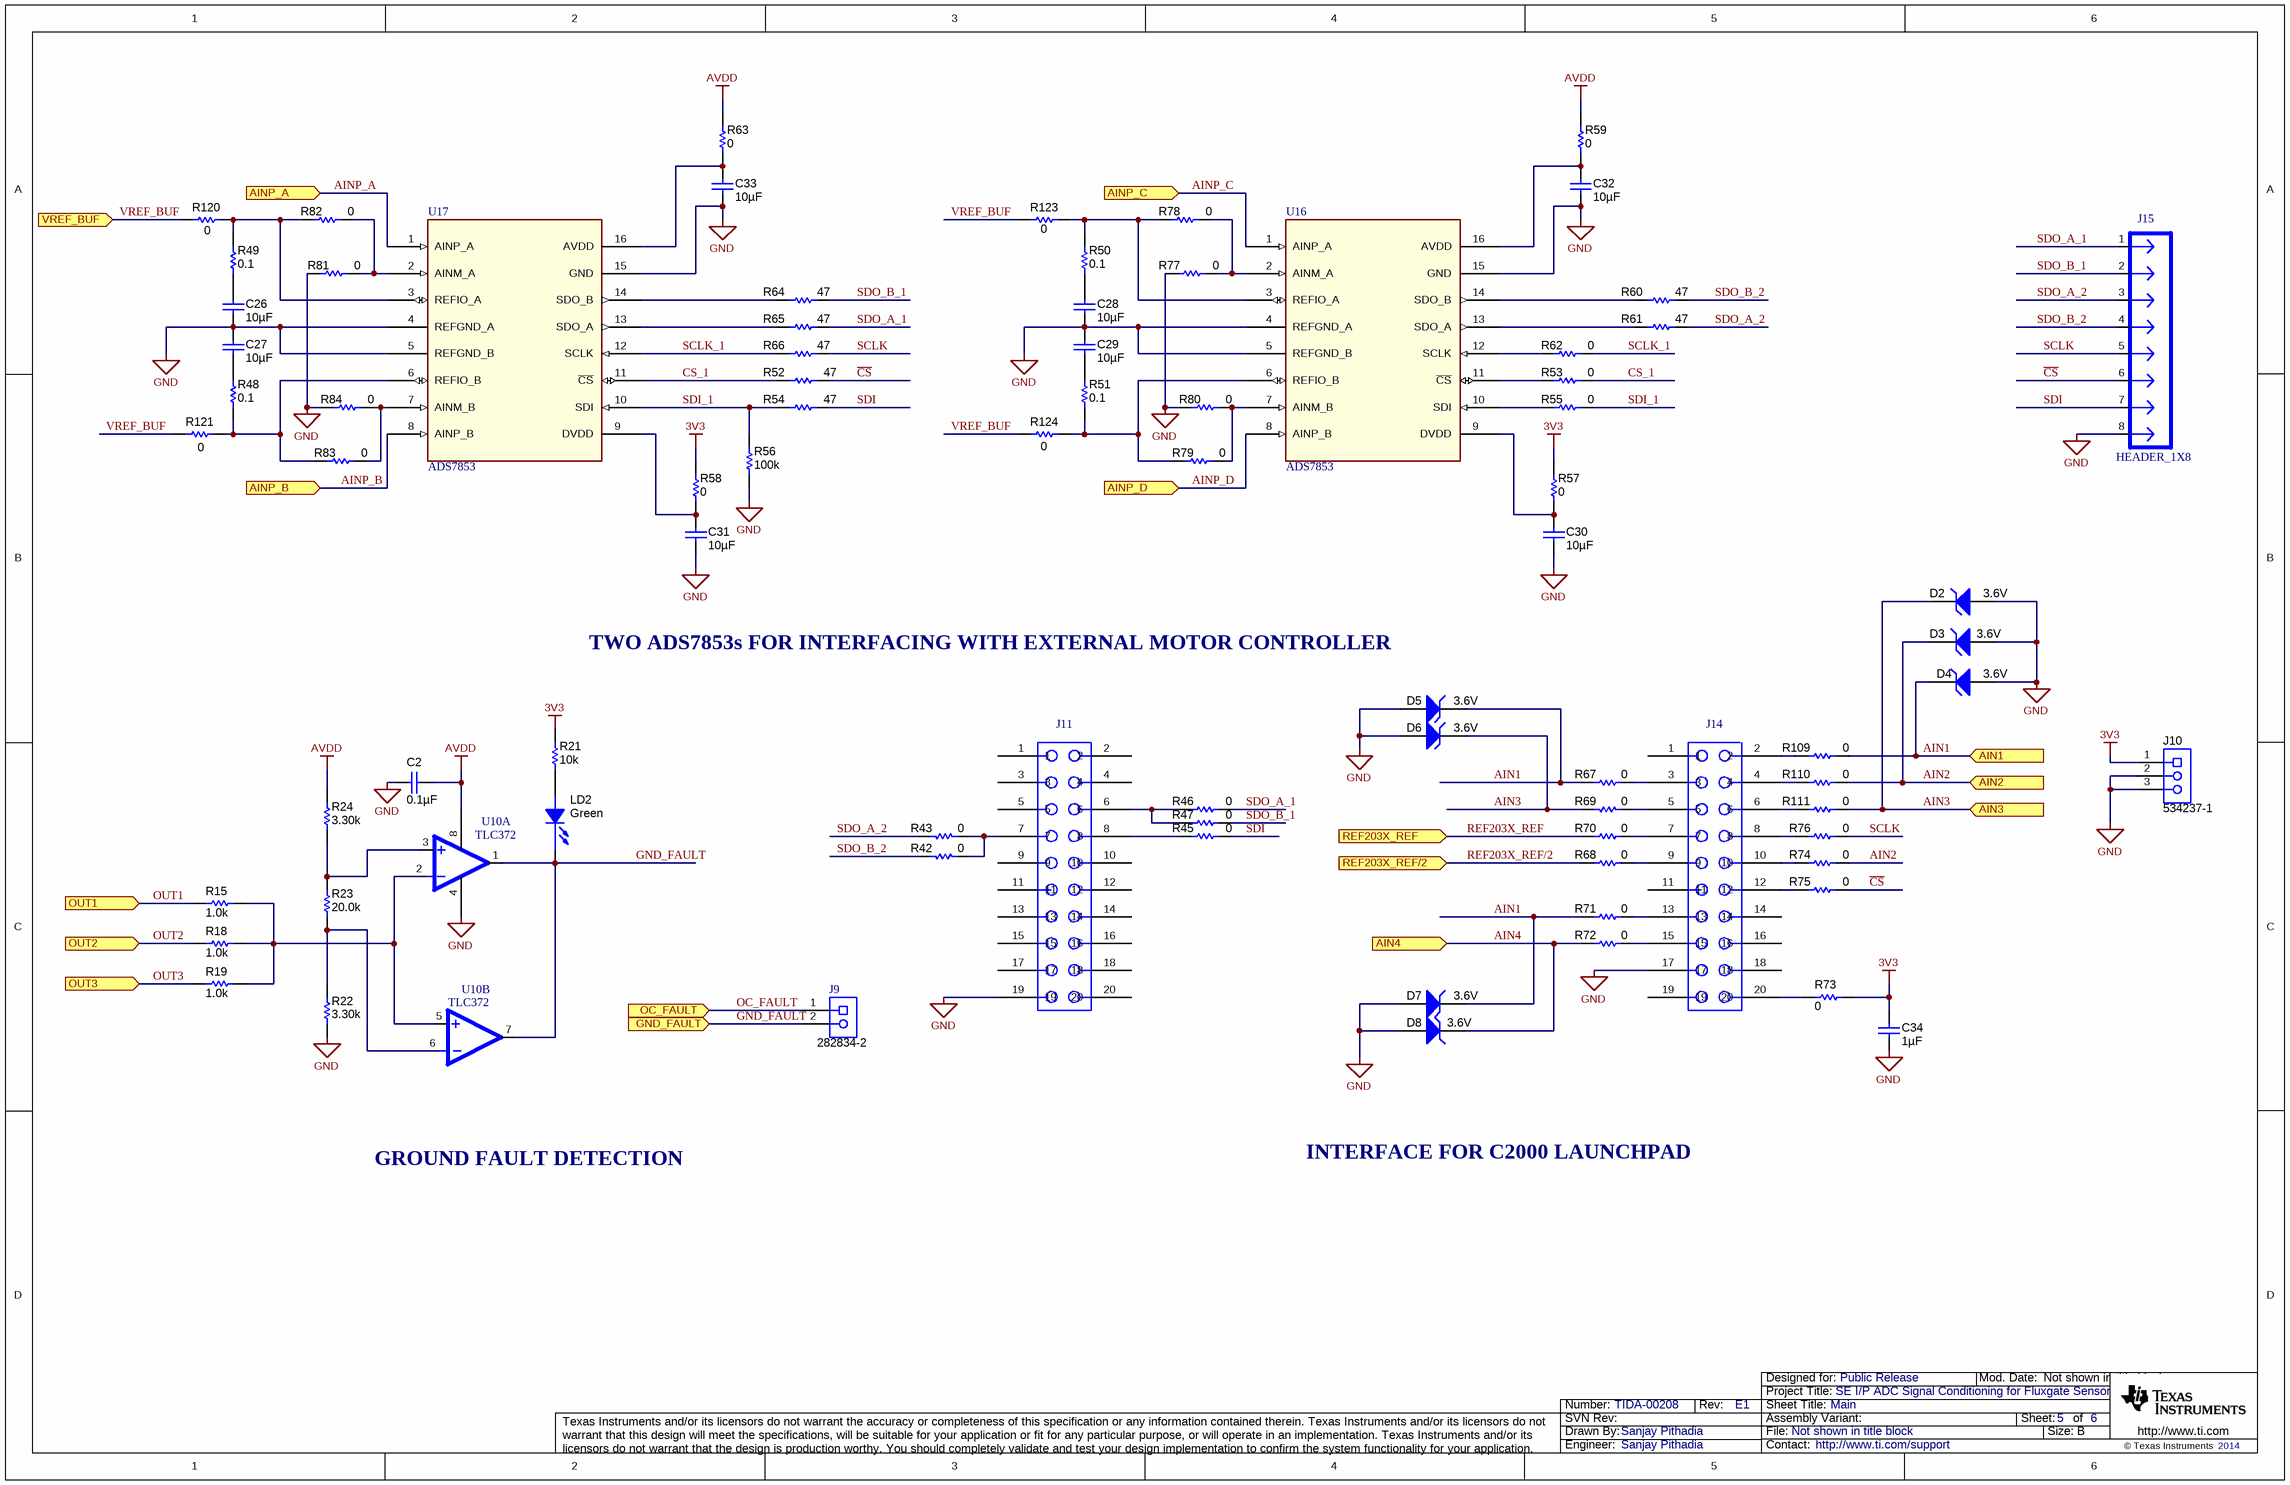
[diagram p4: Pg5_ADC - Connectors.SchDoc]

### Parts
C2  ValueDisplayed: 0.1µF  [0603]  (hidden comment: C0603C104J4RACTU)
C26  ValueDisplayed: 10µF  [0603]  (hidden comment: C1608X5R1E106M080AC)
C27  ValueDisplayed: 10µF  [0603]  (hidden comment: C1608X5R1E106M080AC)
C28  ValueDisplayed: 10µF  [0603]  (hidden comment: C1608X5R1E106M080AC)
C29  ValueDisplayed: 10µF  [0603]  (hidden comment: C1608X5R1E106M080AC)
C30  ValueDisplayed: 10µF  [0603]  (hidden comment: C1608X5R1E106M080AC)
C31  ValueDisplayed: 10µF  [0603]  (hidden comment: C1608X5R1E106M080AC)
C32  ValueDisplayed: 10µF  [0603]  (hidden comment: C1608X5R1E106M080AC)
C33  ValueDisplayed: 10µF  [0603]  (hidden comment: C1608X5R1E106M080AC)
C34  ValueDisplayed: 1µF  [0603]  (hidden comment: GRM188R71E105KA12D)
D2  value 3.6V  [SOD-123]  (hidden comment: MMSZ5227B-7-F)
D3  value 3.6V  [SOD-123]  (hidden comment: MMSZ5227B-7-F)
D4  value 3.6V  [SOD-123]  (hidden comment: MMSZ5227B-7-F)
D5  value 3.6V  [SOD-123]  (hidden comment: MMSZ5227B-7-F)
D6  value 3.6V  [SOD-123]  (hidden comment: MMSZ5227B-7-F)
D7  value 3.6V  [SOD-123]  (hidden comment: MMSZ5227B-7-F)
D8  value 3.6V  [SOD-123]  (hidden comment: MMSZ5227B-7-F)
J9  282834-2  [TEC_282834-2]
J10  534237-1  [CONN_534237-1]
J11  HEADER_NPTC202KFM  [HEADER_NPTC202KFM]  (value not drawn)
J14  HEADER_NPTC202KFM  [HEADER_NPTC202KFM]  (value not drawn)
J15  HEADER_1X8  [HDR100_1X8]
LD2  value Green  [LED0603AA]  (hidden comment: LED_LG L29K-G2J1-24-Z)
R15  value 1.0k  [0603]  (hidden comment: CRCW06031K00JNEA)
R18  value 1.0k  [0603]  (hidden comment: CRCW06031K00JNEA)
R19  value 1.0k  [0603]  (hidden comment: CRCW06031K00JNEA)
R21  value 10k  [0603]  (hidden comment: CRCW060310K0JNEA)
R22  value 3.30k  [0603]  (hidden comment: RC0603FR-073K3L)
R23  value 20.0k  [0603]  (hidden comment: CRCW060320K0FKEA)
R24  value 3.30k  [0603]  (hidden comment: RC0603FR-073K3L)
R42  value 0  [0603]  (hidden comment: CRCW06030000Z0EA)
R43  value 0  [0603]  (hidden comment: CRCW06030000Z0EA)
R45  value 0  [0603]  (hidden comment: CRCW06030000Z0EA)
R46  value 0  [0603]  (hidden comment: CRCW06030000Z0EA)
R47  value 0  [0603]  (hidden comment: CRCW06030000Z0EA)
R48  value 0.1  [0603]  (hidden comment: ERJ-3RSFR10V)
R49  value 0.1  [0603]  (hidden comment: ERJ-3RSFR10V)
R50  value 0.1  [0603]  (hidden comment: ERJ-3RSFR10V)
R51  value 0.1  [0603]  (hidden comment: ERJ-3RSFR10V)
R52  value 47  [0603]  (hidden comment: CRCW060347R0JNEA)
R53  value 0  [0603]  (hidden comment: CRCW06030000Z0EA)
R54  value 47  [0603]  (hidden comment: CRCW060347R0JNEA)
R55  value 0  [0603]  (hidden comment: CRCW06030000Z0EA)
R56  value 100k  [0603]  (hidden comment: CRCW0603100KFKEA)
R57  value 0  [0603]  (hidden comment: CRCW06030000Z0EA)
R58  value 0  [0603]  (hidden comment: CRCW06030000Z0EA)
R59  value 0  [0603]  (hidden comment: CRCW06030000Z0EA)
R60  value 47  [0603]  (hidden comment: CRCW060347R0JNEA)
R61  value 47  [0603]  (hidden comment: CRCW060347R0JNEA)
R62  value 0  [0603]  (hidden comment: CRCW06030000Z0EA)
R63  value 0  [0603]  (hidden comment: CRCW06030000Z0EA)
R64  value 47  [0603]  (hidden comment: CRCW060347R0JNEA)
R65  value 47  [0603]  (hidden comment: CRCW060347R0JNEA)
R66  value 47  [0603]  (hidden comment: CRCW060347R0JNEA)
R67  value 0  [0603]  (hidden comment: CRCW06030000Z0EA)
R68  value 0  [0603]  (hidden comment: CRCW06030000Z0EA)
R69  value 0  [0603]  (hidden comment: CRCW06030000Z0EA)
R70  value 0  [0603]  (hidden comment: CRCW06030000Z0EA)
R71  value 0  [0603]  (hidden comment: CRCW06030000Z0EA)
R72  value 0  [0603]  (hidden comment: CRCW06030000Z0EA)
R73  value 0  [0603]  (hidden comment: CRCW06030000Z0EA)
R74  value 0  [0603]  (hidden comment: CRCW06030000Z0EA)
R75  value 0  [0603]  (hidden comment: CRCW06030000Z0EA)
R76  value 0  [0603]  (hidden comment: CRCW06030000Z0EA)
R77  value 0  [0603]  (hidden comment: CRCW06030000Z0EA)
R78  value 0  [0603]  (hidden comment: CRCW06030000Z0EA)
R79  value 0  [0603]  (hidden comment: CRCW06030000Z0EA)
R80  value 0  [0603]  (hidden comment: CRCW06030000Z0EA)
R81  value 0  [0603]  (hidden comment: CRCW06030000Z0EA)
R82  value 0  [0603]  (hidden comment: CRCW06030000Z0EA)
R83  value 0  [0603]  (hidden comment: CRCW06030000Z0EA)
R84  value 0  [0603]  (hidden comment: CRCW06030000Z0EA)
R109  value 0  [0603]  (hidden comment: CRCW06030000Z0EA)
R110  value 0  [0603]  (hidden comment: CRCW06030000Z0EA)
R111  value 0  [0603]  (hidden comment: CRCW06030000Z0EA)
R120  value 0  [0603]  (hidden comment: CRCW06030000Z0EA)
R121  value 0  [0603]  (hidden comment: CRCW06030000Z0EA)
R123  value 0  [0603]  (hidden comment: CRCW06030000Z0EA)
R124  value 0  [0603]  (hidden comment: CRCW06030000Z0EA)
U10  TLC372  [SO8]  (parts A,B of 2)
U16  ADS7853  [PW16]
U17  ADS7853  [PW16]

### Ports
AIN1 (in), AIN2 (in), AIN3 (in), AIN4 (in), AINP_A (in), AINP_B (in), AINP_C (in), AINP_D (in), GND_FAULT (in), OC_FAULT (in), OUT1 (in), OUT2 (in), OUT3 (in), REF203X_REF (in), REF203X_REF/2 (in), VREF_BUF (in)

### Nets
3V3: C34.1 J10.1 R21.2 R57.2 R58.2 R73.2
AVDD: C2.1 R24.2 R59.2 R63.2 U10.8(VCC)
GND: C2.2 C26.2 C27.1 C28.2 C29.1 C30.2 C31.2 C32.2 C33.2 C34.2 D2.2(A) D3.2(A) D4.2(A) D5.2(A) D6.2(A) D7.2(A) D8.2(A) J10.2 J10.3 J11.19 J14.17 J15.8 R22.1 R56.1 R77.2 R80.2 R81.2 R84.2 U10.4(GND) U16.4(REFGND_A) U16.5(REFGND_B) U16.15(GND) U17.4(REFGND_A) U17.5(REFGND_B) U17.15(GND)
~{CS}: J15.6 R52.2 R75.1
AIN1: D4.1(K) D5.1(K) D7.1(K) R67.2 R71.2 R109.1 ; port AIN1
AIN2: D3.1(K) R74.1 R110.1 ; port AIN2
AIN3: D2.1(K) D6.1(K) R69.1 R111.1 ; port AIN3
AIN4: D8.1(K) R72.2 ; port AIN4
AINP_A: U17.1(AINP_A) ; port AINP_A
AINP_B: U17.8(AINP_B) ; port AINP_B
AINP_C: U16.1(AINP_A) ; port AINP_C
AINP_D: U16.8(AINP_B) ; port AINP_D
CS_1: R52.1 R53.1 U17.11(~{CS})
GND_FAULT: J9.2 LD2.1(C) U10.1(OUT) U10.7(OUT) ; port GND_FAULT
OC_FAULT: J9.1 ; port OC_FAULT
OUT1: R15.1 ; port OUT1
OUT2: R18.1 ; port OUT2
OUT3: R19.1 ; port OUT3
REF203X_REF: R70.1 ; port REF203X_REF
REF203X_REF/2: R68.1 ; port REF203X_REF/2
SCLK: J15.5 R66.2 R76.1
SCLK_1: R62.1 R66.1 U17.12(SCLK)
SDI: J15.7 R45.1 R54.2
SDI_1: R54.1 R55.1 R56.2 U17.10(SDI)
SDO_A_1: J15.1 R46.1 R65.2
SDO_A_2: J15.3 R43.1 R61.2
SDO_B_1: J15.2 R47.1 R64.2
SDO_B_2: J15.4 R42.1 R60.2
VREF_BUF: R120.2 R121.2 R123.2 R124.2 ; port VREF_BUF
NetC26_1: C26.1 R49.1
NetC27_2: C27.2 R48.2
NetC28_1: C28.1 R50.1
NetC29_2: C29.2 R51.2
NetC30_1: C30.1 R57.1 U16.9(DVDD)
NetC31_1: C31.1 R58.1 U17.9(DVDD)
NetC32_1: C32.1 R59.1 U16.16(AVDD)
NetC33_1: C33.1 R63.1 U17.16(AVDD)
NetJ11_6: J11.6 R46.2 R47.2
NetJ11_7: J11.7 R42.2 R43.2
NetJ11_8: J11.8 R45.2
NetJ14_2: J14.2 R109.2
NetJ14_3: J14.3 R67.1
NetJ14_4: J14.4 R110.2
NetJ14_5: J14.5 R69.2
NetJ14_6: J14.6 R111.2
NetJ14_7: J14.7 R70.2
NetJ14_8: J14.8 R76.2
NetJ14_9: J14.9 R68.2
NetJ14_10: J14.10 R74.2
NetJ14_12: J14.12 R75.2
NetJ14_13: J14.13 R71.1
NetJ14_15: J14.15 R72.1
NetJ14_20: J14.20 R73.1
NetLD2_2: LD2.2(A) R21.1
NetR15_2: R15.2 R18.2 R19.2 U10.2(IN-) U10.5(IN+)
NetR22_2: R22.2 R23.1 U10.6(IN-)
NetR23_2: R23.2 R24.1 U10.3(IN+)
NetR48_1: R48.1 R83.2 R121.1 U17.6(REFIO_B)
NetR49_2: R49.2 R82.2 R120.1 U17.3(REFIO_A)
NetR50_2: R50.2 R78.2 R123.1 U16.3(REFIO_A)
NetR51_1: R51.1 R79.2 R124.1 U16.6(REFIO_B)
NetR53_2: R53.2 U16.11(~{CS})
NetR55_2: R55.2 U16.10(SDI)
NetR60_1: R60.1 U16.14(SDO_B)
NetR61_1: R61.1 U16.13(SDO_A)
NetR62_2: R62.2 U16.12(SCLK)
NetR64_1: R64.1 U17.14(SDO_B)
NetR65_1: R65.1 U17.13(SDO_A)
NetR77_1: R77.1 R78.1 U16.2(AINM_A)
NetR79_1: R79.1 R80.1 U16.7(AINM_B)
NetR81_1: R81.1 R82.1 U17.2(AINM_A)
NetR83_1: R83.1 R84.1 U17.7(AINM_B)

Not connected (* = marked no-connect by the designer): J11 1 2 3 4 5 9 10 11 12 13 14 15 16 17 18 20; J14 1 11 14 16 18 19

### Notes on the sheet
- TWO ADS7853s FOR INTERFACING WITH EXTERNAL MOTOR CONTROLLER
- GROUND FAULT DETECTION
- INTERFACE FOR C2000 LAUNCHPAD

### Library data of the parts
C2 = C0603C104J4RACTU: as C1 on sheet Pg2_Power
C26-C33 = C1608X5R1E106M080AC: CAP, CERM, 10uF, 25V, +/-20%, X5R, 0603; Manufacturer: TDK; Polarized: N; CompType: Capacitor; U/M: EA; Cap_F: 0.00001; Tolerance_%: 20; Value1: Unknown; VDC_V: 25; TaMin_C: -55; TaMax_C: 85
C34 = GRM188R71E105KA12D: as C54 on sheet Pg3_Channel-1_2
D2-D8 = MMSZ5227B-7-F: Diode, Zener, 3.6V, 500mW, SOD-123; Manufacturer: Diodes Inc.; SymbolCreator: a0412235; U/M: EA; Power_W: 0.5; Vz_V: 3.6; Value1: 0.5W; RJA_CperW: 350
J9 = 282834-2: Terminal Block, 2x1, 2.54mm, TH; Manufacturer: TE Connectivity; SymbolCreator: a0412235; U/M: EA
J10 = 534237-1: Receptacle, 100mil, 3x1, TH; Manufacturer: TE Connectivity; SymbolCreator: a0412235; U/M: EA
J11 J14 = HEADER_NPTC202KFM: CONN RCPT 20POS .100 DL STR SMD; PartNumber: 89898-310ALF; Manufacturer: FCI; Vendor Part #: 609-4473-1-ND; Second Source: C:\program files\p-cad 2004\HEADER_NPTC-SERIES.pdf; Reference: \\vette02\pmp_pcb\pcad_pdf's\HEADER_NPTC-SERIES.pdf; Area: 363000; Value: 20-Pin/2-Row; Vendor: DigiKey
J15 = HEADER_1X8: Header, Male 8-pin, 100mil spacing,; Manufacturer: Sullins; PartNumber: PEC08SAAN; area: 88000; Value: PEC08SAAN
LD2 = LED_LG L29K-G2J1-24-Z: as LD3 on sheet Pg2_Power
R15 R18 R19 = CRCW06031K00JNEA: RES, 1.0k ohm, 5%, 0.1W, 0603; Manufacturer: Vishay-Dale; CompType: Resistor; Res_ohm: 1000; Value_Code: 1k00; Tolerance_%: 5; Power_W: 0.1; VDC_V: 75; TempCo: 200 ppm/C; EIA_Code: E24; U/M: EA
R21 = CRCW060310K0JNEA: as R34 on sheet Pg2_Power
R22 R24 = RC0603FR-073K3L: as R7 on sheet Pg3_Channel-1_2
R23 = CRCW060320K0FKEA: as R8 on sheet Pg3_Channel-1_2
R42 R43 R45-R47 R53 R55 R57-R59 R62 R63 R67-R84 R109-R111 R120 R121 R123 R124 = CRCW06030000Z0EA: as R14 on sheet Pg2_Power
R48-R51 = ERJ-3RSFR10V: RES, 0.1 ohm, 1%, 0.1W, 0603; Manufacturer: Panasonic; CompType: Resistor; Value_Code: R100; Tolerance_%: 1; TempCo: 300 ppm/C; EIA_Code: E96; U/M: EA
R52 R54 R60 R61 R64-R66 = CRCW060347R0JNEA: RES, 47 ohm, 5%, 0.1W, 0603; Manufacturer: Vishay-Dale; CompType: Resistor; Value_Code: 47R0; Tolerance_%: 5; Power_W: 0.1; VDC_V: 75; TempCo: 200 ppm/C; EIA_Code: E24; U/M: EA
R56 = CRCW0603100KFKEA: RES, 100k ohm, 1%, 0.1W, 0603; Manufacturer: Vishay-Dale; CompType: Resistor; Res_ohm: 100000; Tolerance_%: 1; Power_W: 0.1; VDC_V: 75; TempCo: 100 ppm/C; EIA_Code: E96; U/M: EA
U10 = LM393D: as U8 on sheet Pg3_Channel-1_2
U16 U17 = ADS7853: IC ADC 12BIT 1MSPS DUAL 16TSSOP; Manufacturer: Texas Instruments; SymbolCreator: x0213103

## Sheet Pg6_Hardware_ANSI-B.SchDoc
size 431 x 279 mm; Date: Not shown in title block; ApprovedBy: Not shown in title block; CheckedBy: Not shown in title block; Author: Not shown in title block; CompanyName: Not shown in title block; Engineer: Not shown in title block; Organization: Not shown in title block; Address1: Not shown in title block; Address2: Not shown in title block; Address3: Not shown in title block; Address4: Not shown in title block; DocumentNumber: 6; Revision: Use project parameter SCH_Rev; SheetNumber: 6; SheetTotal: 6; PageSetup: Record=PageOptions|CenterHorizontal=True|CenterVertical=True|PrintScale=1.00|XCorrection=1.00|YCorrection=1.00|PrintKind=0|BorderSize=5000000|LeftOffset=0|BottomOffset=0|Orientation=2|PaperLength=1000|PaperWidth=1000|Scale=100|PaperSource=15|PrintQuality=600|MediaType=1|DitherType=10|PaperKind=Letter|PrintScaleMode=1
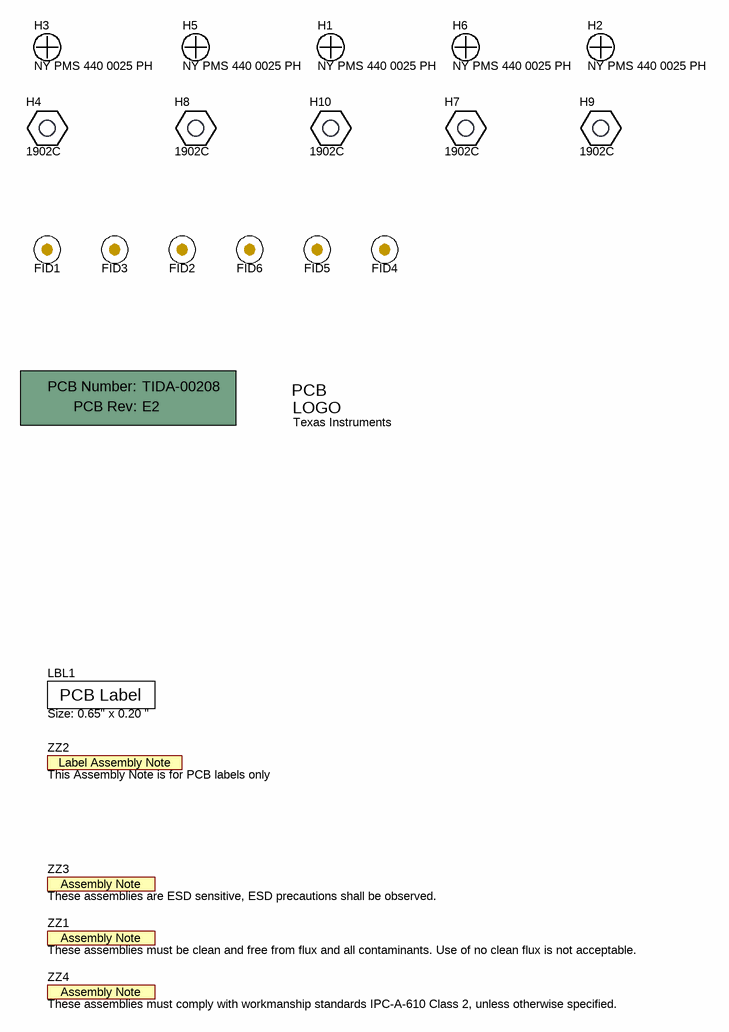
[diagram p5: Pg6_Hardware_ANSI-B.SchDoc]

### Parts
!PCB  Printed Circuit Board  (value not drawn)  (mechanical)
FID1  Fiducial  [Fiducial10-20]  (value not drawn)
FID2  Fiducial  [Fiducial10-20]  (value not drawn)
FID3  Fiducial  [Fiducial10-20]  (value not drawn)
FID4  Fiducial  [Fiducial10-20]  (value not drawn)
FID5  Fiducial  [Fiducial10-20]  (value not drawn)
FID6  Fiducial  [Fiducial10-20]  (value not drawn)
H1  NY PMS 440 0025 PH  [NY PMS 440 0025 PH]
H2  NY PMS 440 0025 PH  [NY PMS 440 0025 PH]
H3  NY PMS 440 0025 PH  [NY PMS 440 0025 PH]
H4  1902C  [Keystone_1902C]
H5  NY PMS 440 0025 PH  [NY PMS 440 0025 PH]
H6  NY PMS 440 0025 PH  [NY PMS 440 0025 PH]
H7  1902C  [Keystone_1902C]
H8  1902C  [Keystone_1902C]
H9  1902C  [Keystone_1902C]
H10  1902C  [Keystone_1902C]
LBL1  Size: 0.65" x 0.20 "  [Label_650x200]
Logo1  Texas Instruments  [TI_Stacked_SolderMask_Small]  (no BOM)
ZZ1  These assemblies must be clean and free from flux and all contaminants. Use of no clean flux is not acceptable.  [AssemblyNote]  (no BOM)
ZZ2  This Assembly Note is for PCB labels only  [AssemblyNoteLabel]  (no BOM)
ZZ3  These assemblies are ESD sensitive, ESD precautions shall be observed.  [AssemblyNote]  (no BOM)
ZZ4  These assemblies must comply with workmanship standards IPC-A-610 Class 2, unless otherwise specified.  [AssemblyNote]  (no BOM)

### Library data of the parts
!PCB = PCB: Manufacturer: Any; PartNumber: TIDA-00208; SymbolCreator: a0412235
FID1-FID6 = Fiducial: Fiducial mark.  There is nothing to buy or mount.; SymbolCreator: codlsc
H1-H3 H5 H6 = NY PMS 440 0025 PH: Machine Screw, Round, #4-40 x 1/4, Nylon, Philips panhead; Manufacturer: B&F Fastener Supply; CompType: Hardware; SymbolCreator: codlsc; U/M: EA
H4 H7-H10 = 1902C: Standoff, Hex, 0.5"L #4-40 Nylon; Manufacturer: Keystone; CompType: Hardware
LBL1 = THT-14-423-10: Thermal Transfer Printable Labels, 0.650" W x 0.200" H - 10,000 per roll; Manufacturer: Brady; SymbolCreator: a0412235; CompType: Label
Logo1 = TI_Logo: Texas Instrument Corporate Signature; SymbolCreator: codlsc
ZZ1 ZZ3 ZZ4 = AssemblyNote: SymbolCreator: codlsc
ZZ2 = AssemblyNoteLabel: SymbolCreator: a0412235

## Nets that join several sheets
3V3: Pg2_Power (C21.1 U14.5), Pg4_Channel-3_4 (R16.2), Pg5_ADC - Connectors (6 pins)
AVDD: Pg2_Power (18 pins), Pg3_Channel-1_2 (12 pins), Pg4_Channel-3_4 (11 pins), Pg5_ADC - Connectors (5 pins)
GND: Pg2_Power (32 pins), Pg3_Channel-1_2 (26 pins), Pg4_Channel-3_4 (25 pins), Pg5_ADC - Connectors (35 pins)
AIN1: Pg3_Channel-1_2 (R91.2), Pg5_ADC - Connectors (6 pins)
AIN2: Pg3_Channel-1_2 (R93.2), Pg5_ADC - Connectors (D3.1 R74.1 R110.1)
AIN3: Pg4_Channel-3_4 (R89.2), Pg5_ADC - Connectors (D2.1 D6.1 R69.1 R111.1)
AIN4: Pg4_Channel-3_4 (R87.2), Pg5_ADC - Connectors (D8.1 R72.2)
AINP_A: Pg3_Channel-1_2 (R90.2), Pg5_ADC - Connectors (U17.1)
AINP_B: Pg3_Channel-1_2 (R92.2), Pg5_ADC - Connectors (U17.8)
AINP_C: Pg4_Channel-3_4 (R88.2), Pg5_ADC - Connectors (U16.1)
AINP_D: Pg4_Channel-3_4 (R86.2), Pg5_ADC - Connectors (U16.8)
OC_FAULT: Pg3_Channel-1_2 (U8.1 U8.7 U9.1 U9.7), Pg4_Channel-3_4 (5 pins), Pg5_ADC - Connectors (J9.1)
OUT1: Pg3_Channel-1_2 (R30.1 U4.12 U9.2 U9.5), Pg5_ADC - Connectors (R15.1)
OUT2: Pg3_Channel-1_2 (R37.1 U3.12 U8.2 U8.5), Pg5_ADC - Connectors (R18.1)
OUT3: Pg4_Channel-3_4 (R98.1 U2.12 U7.2 U7.5), Pg5_ADC - Connectors (R19.1)
REF203X_REF: Pg2_Power (C51.2 R20.1), Pg5_ADC - Connectors (R70.1)
REF203X_REF/2: Pg2_Power (C44.2 R27.1), Pg3_Channel-1_2 (R99.1 R102.1), Pg4_Channel-3_4 (R100.1 R101.1), Pg5_ADC - Connectors (R68.1)
VREF_BUF: Pg2_Power (R103.1), Pg3_Channel-1_2 (R32.1 R36.1 R107.2 R108.2), Pg4_Channel-3_4 (R33.1 R35.1 R105.2 R106.2), Pg5_ADC - Connectors (R120.2 R121.2 R123.2 R124.2)

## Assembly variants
001: not fitted C11 C13 C17 C18 R17 R42 R47 R56 R67 R69 R71 R74 R99 R100 R101 R102 R120 R121 R123 R124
